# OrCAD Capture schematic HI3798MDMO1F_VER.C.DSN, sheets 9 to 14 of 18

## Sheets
9 SHEET_10: size A3
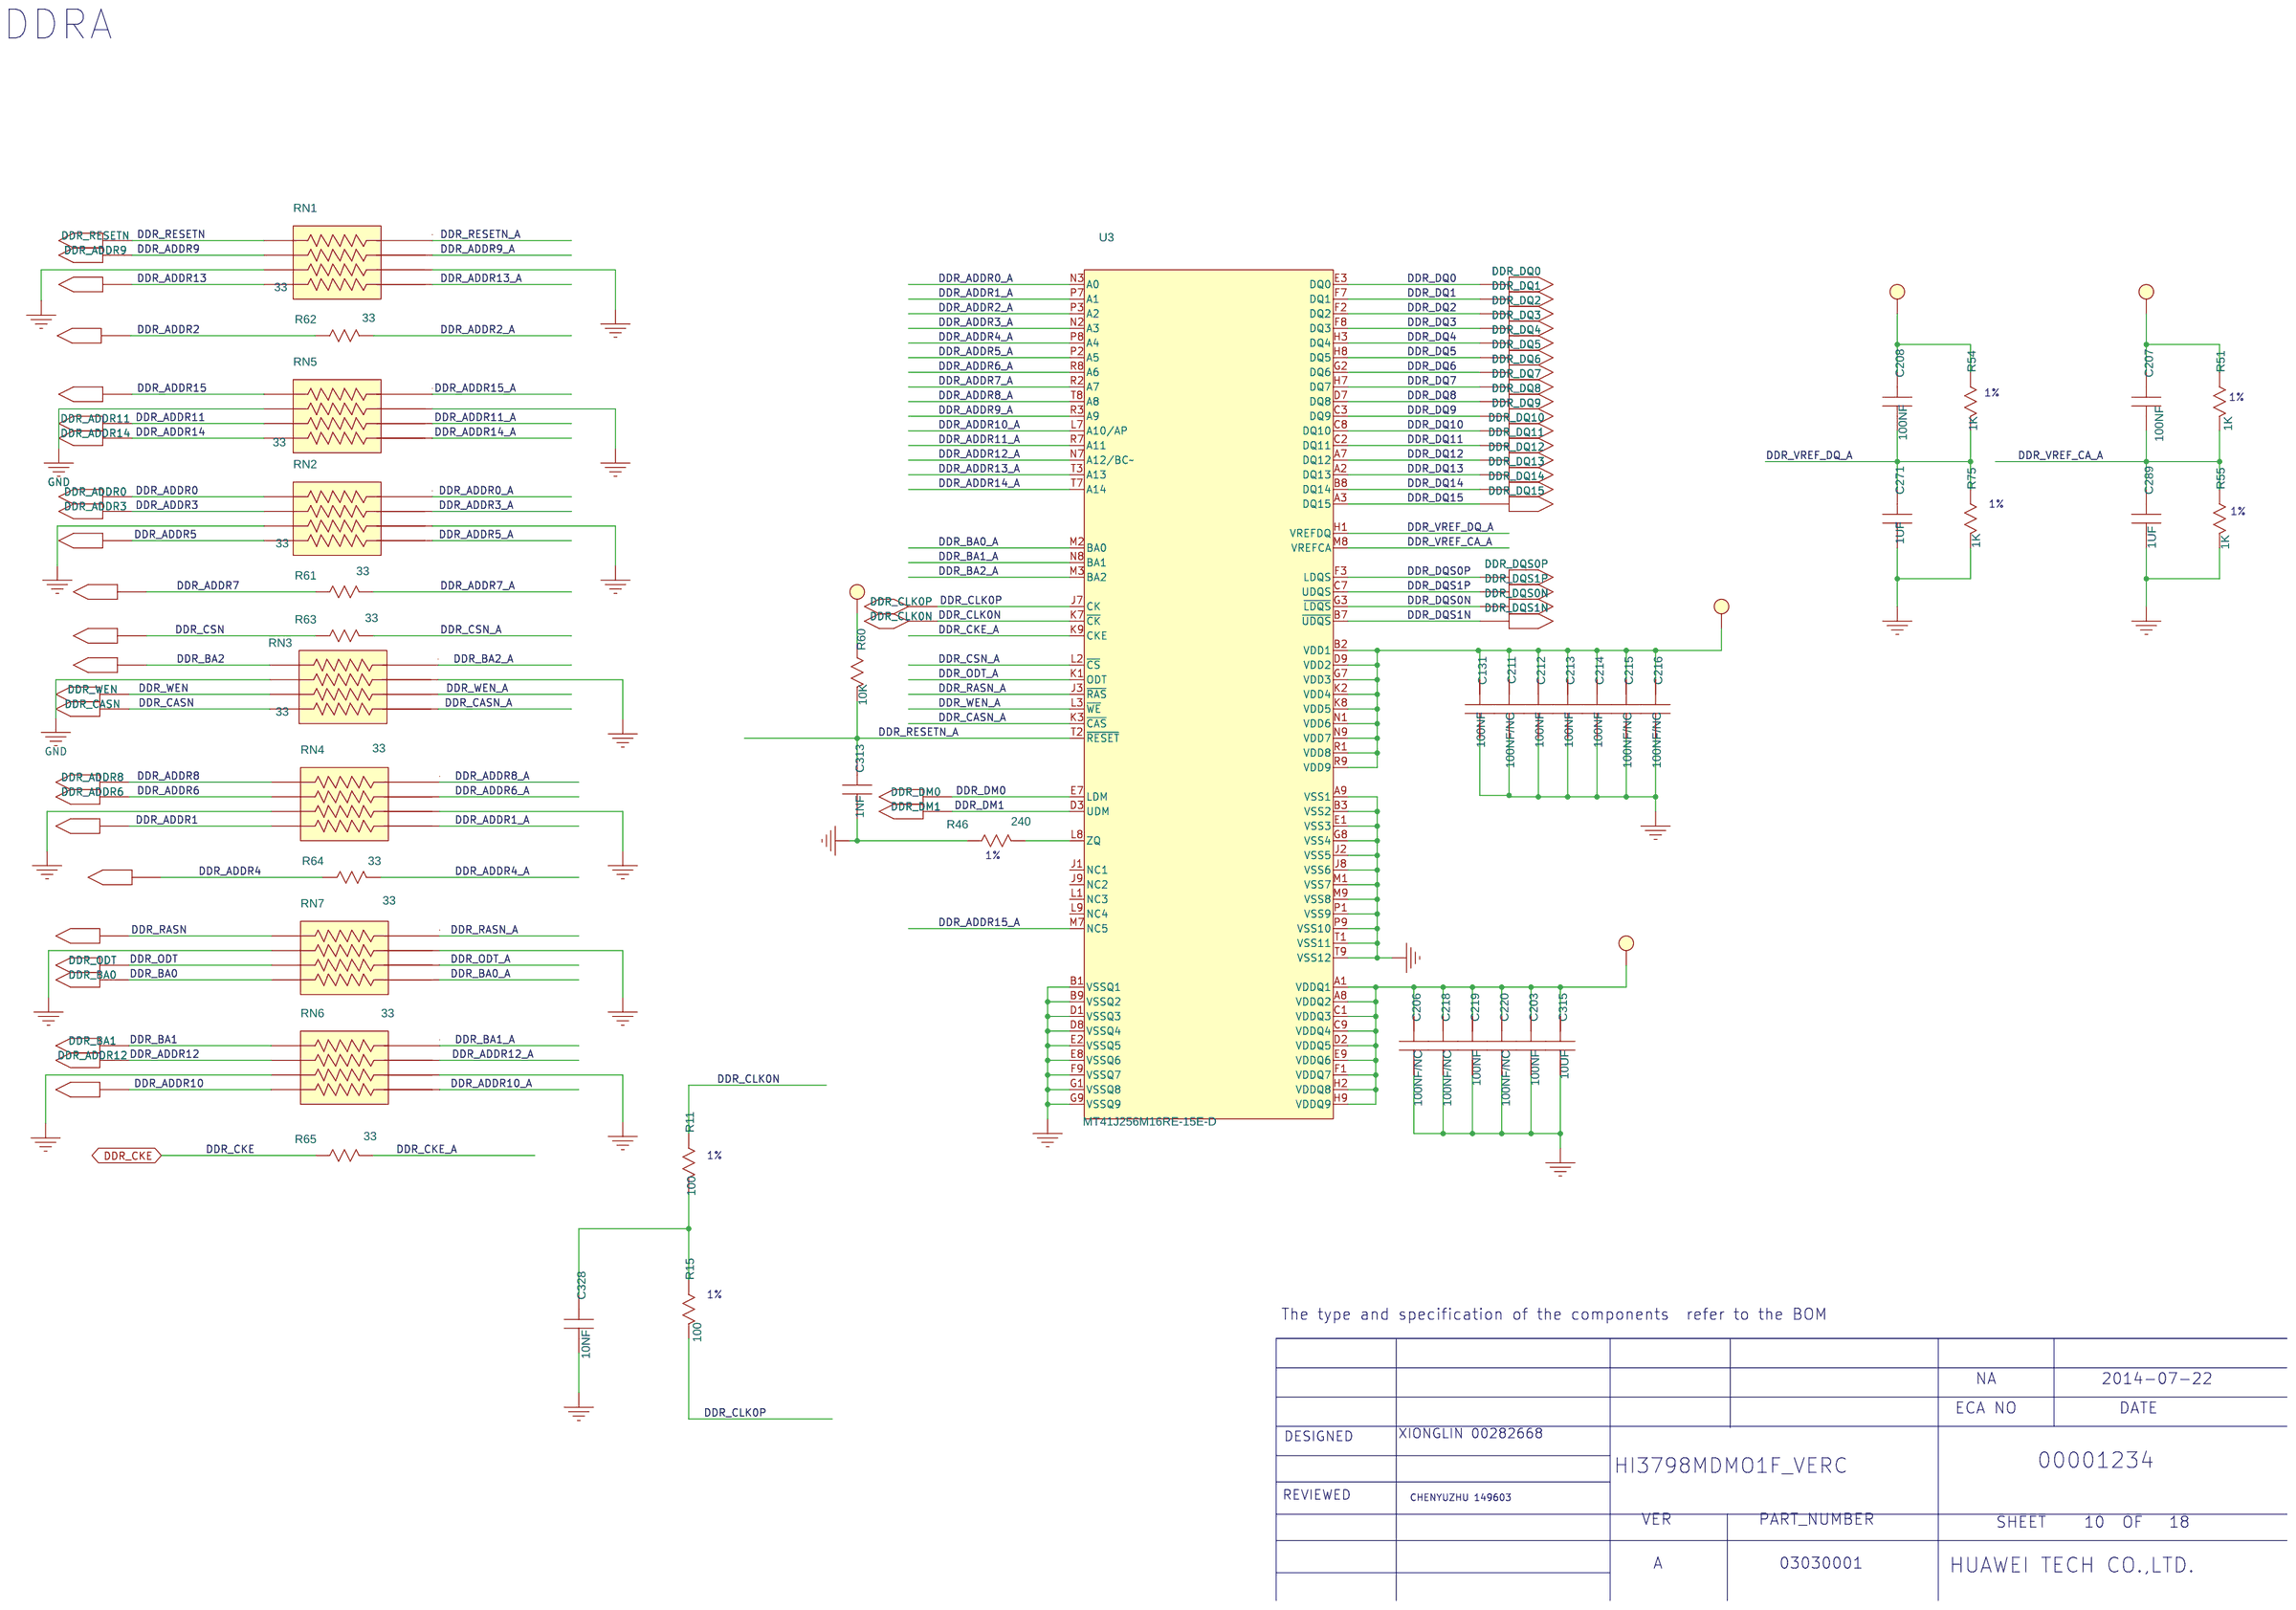
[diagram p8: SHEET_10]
10 SHEET_09: size A3
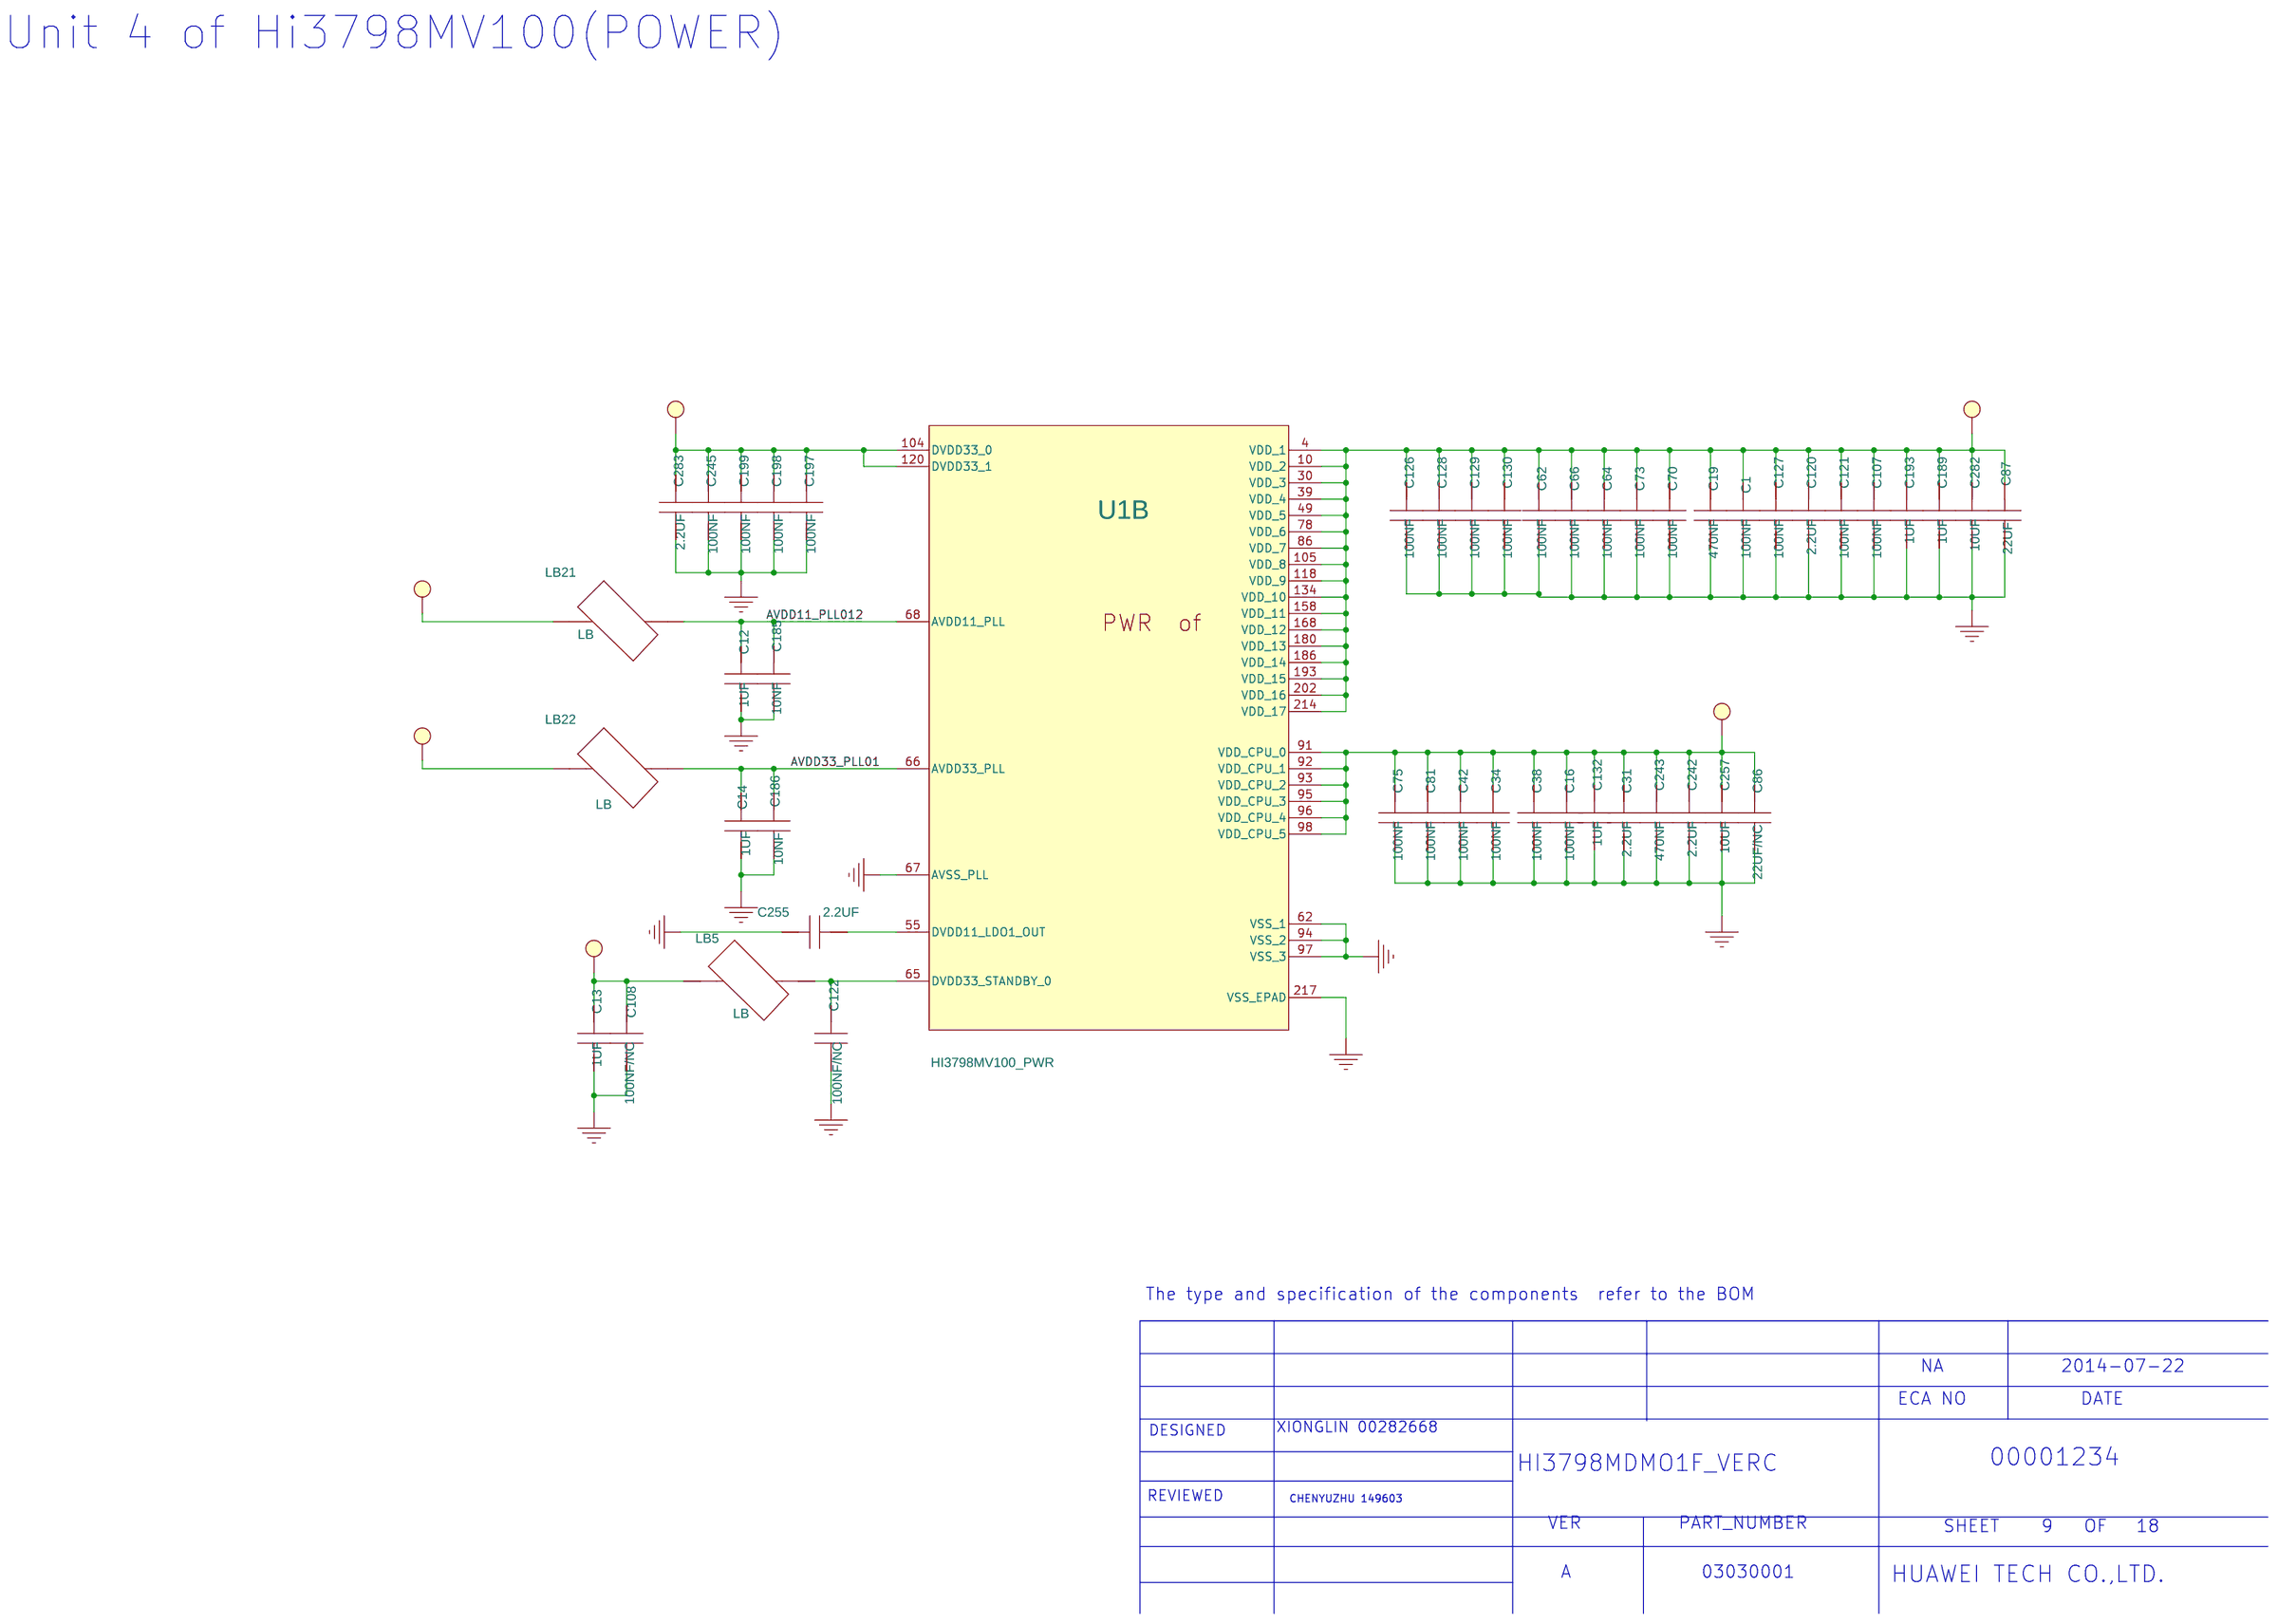
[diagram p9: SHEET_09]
11 SHEET_08: size A3
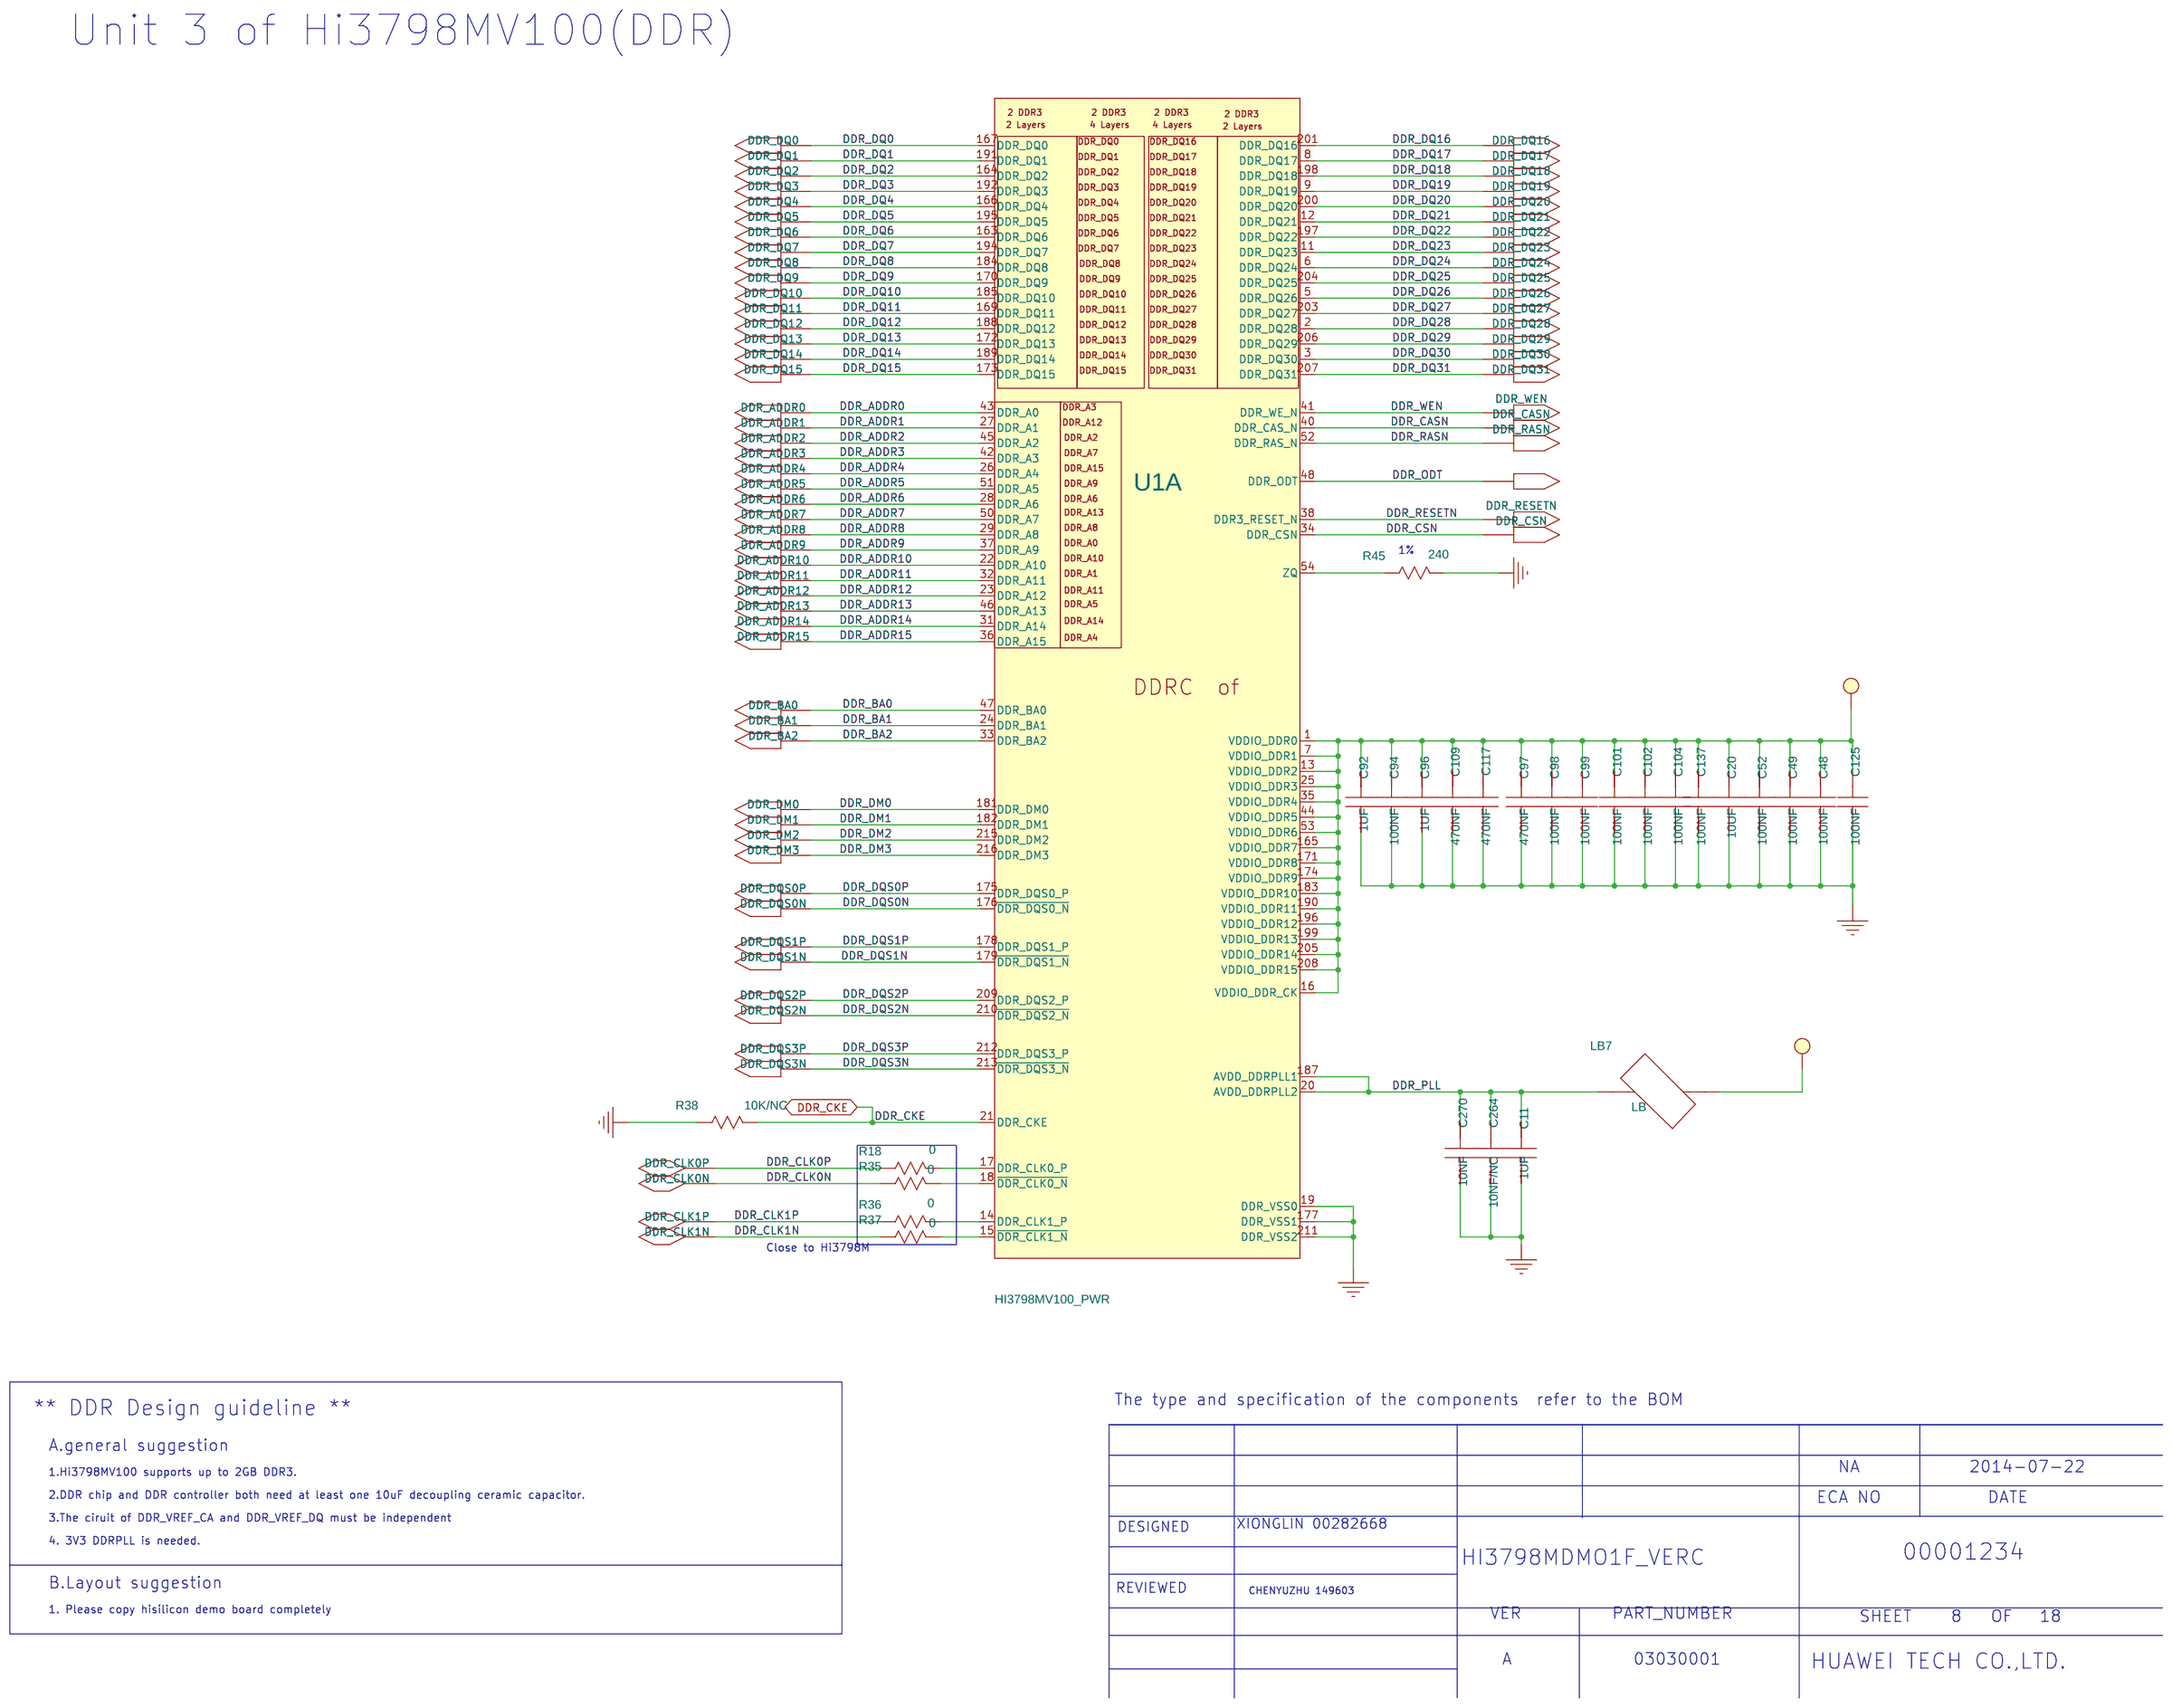
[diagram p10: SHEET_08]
12 SHEET_07: size A3
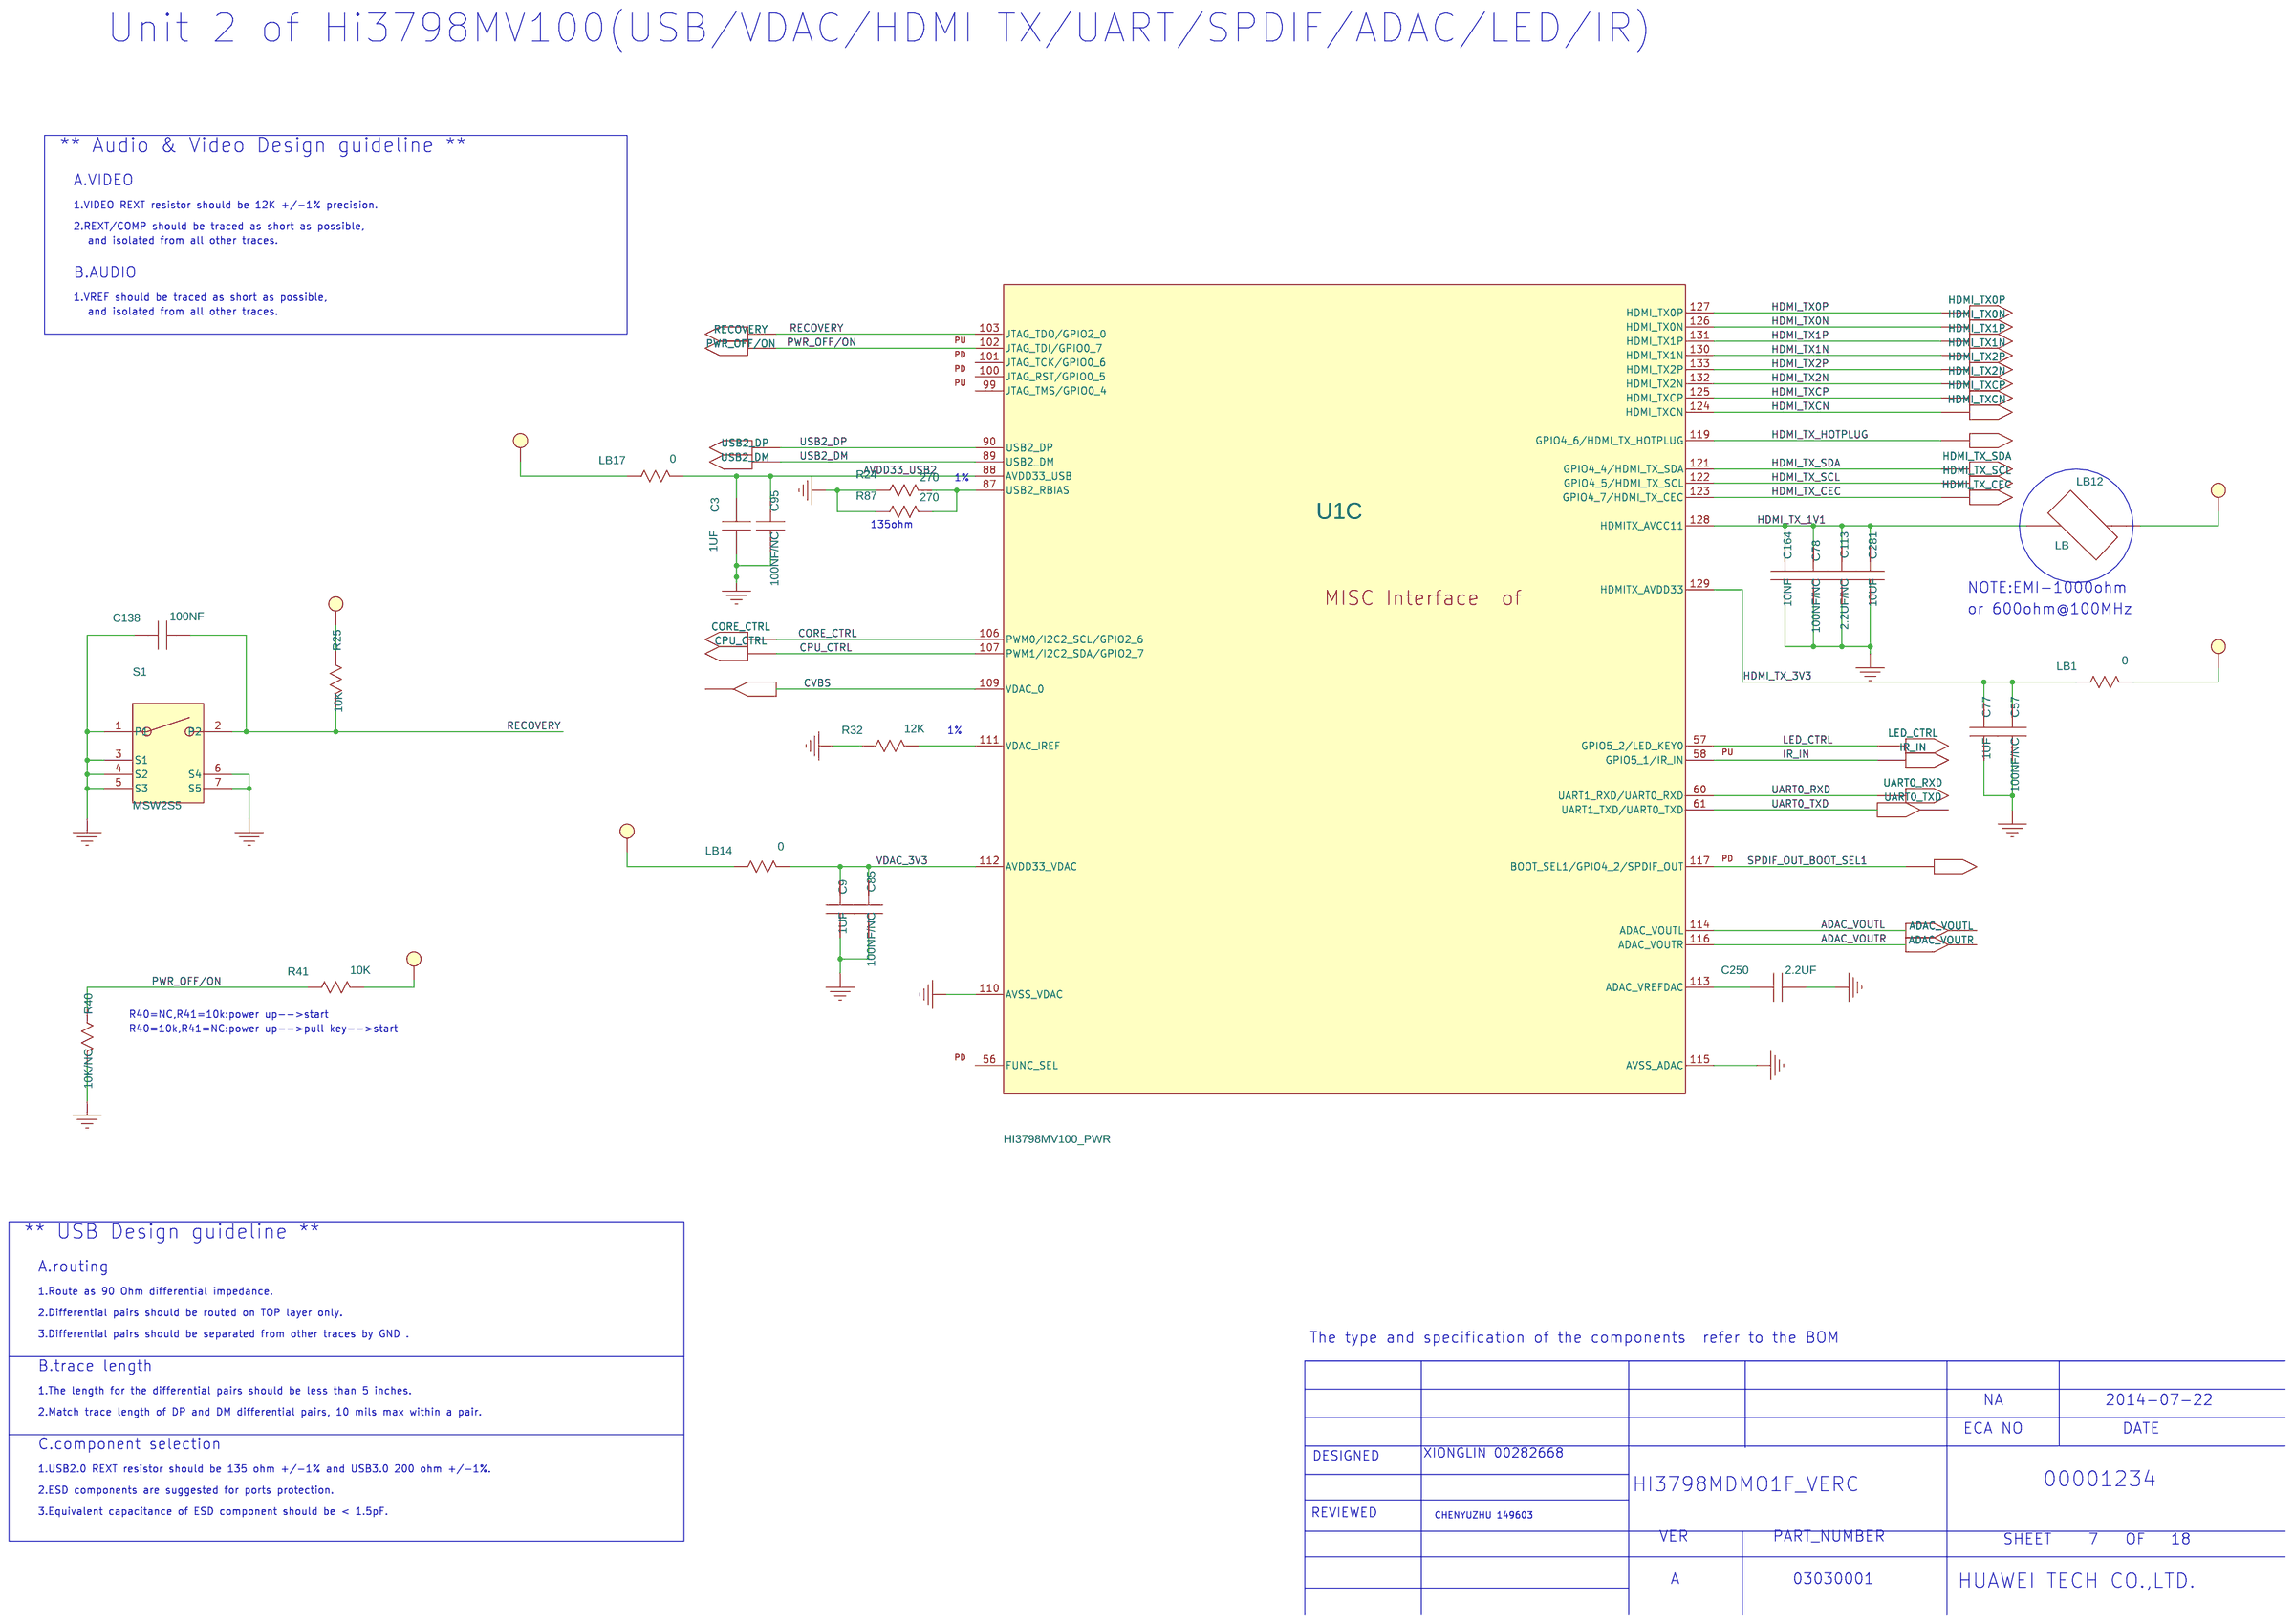
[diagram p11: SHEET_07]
13 SHEET_06: size Custom
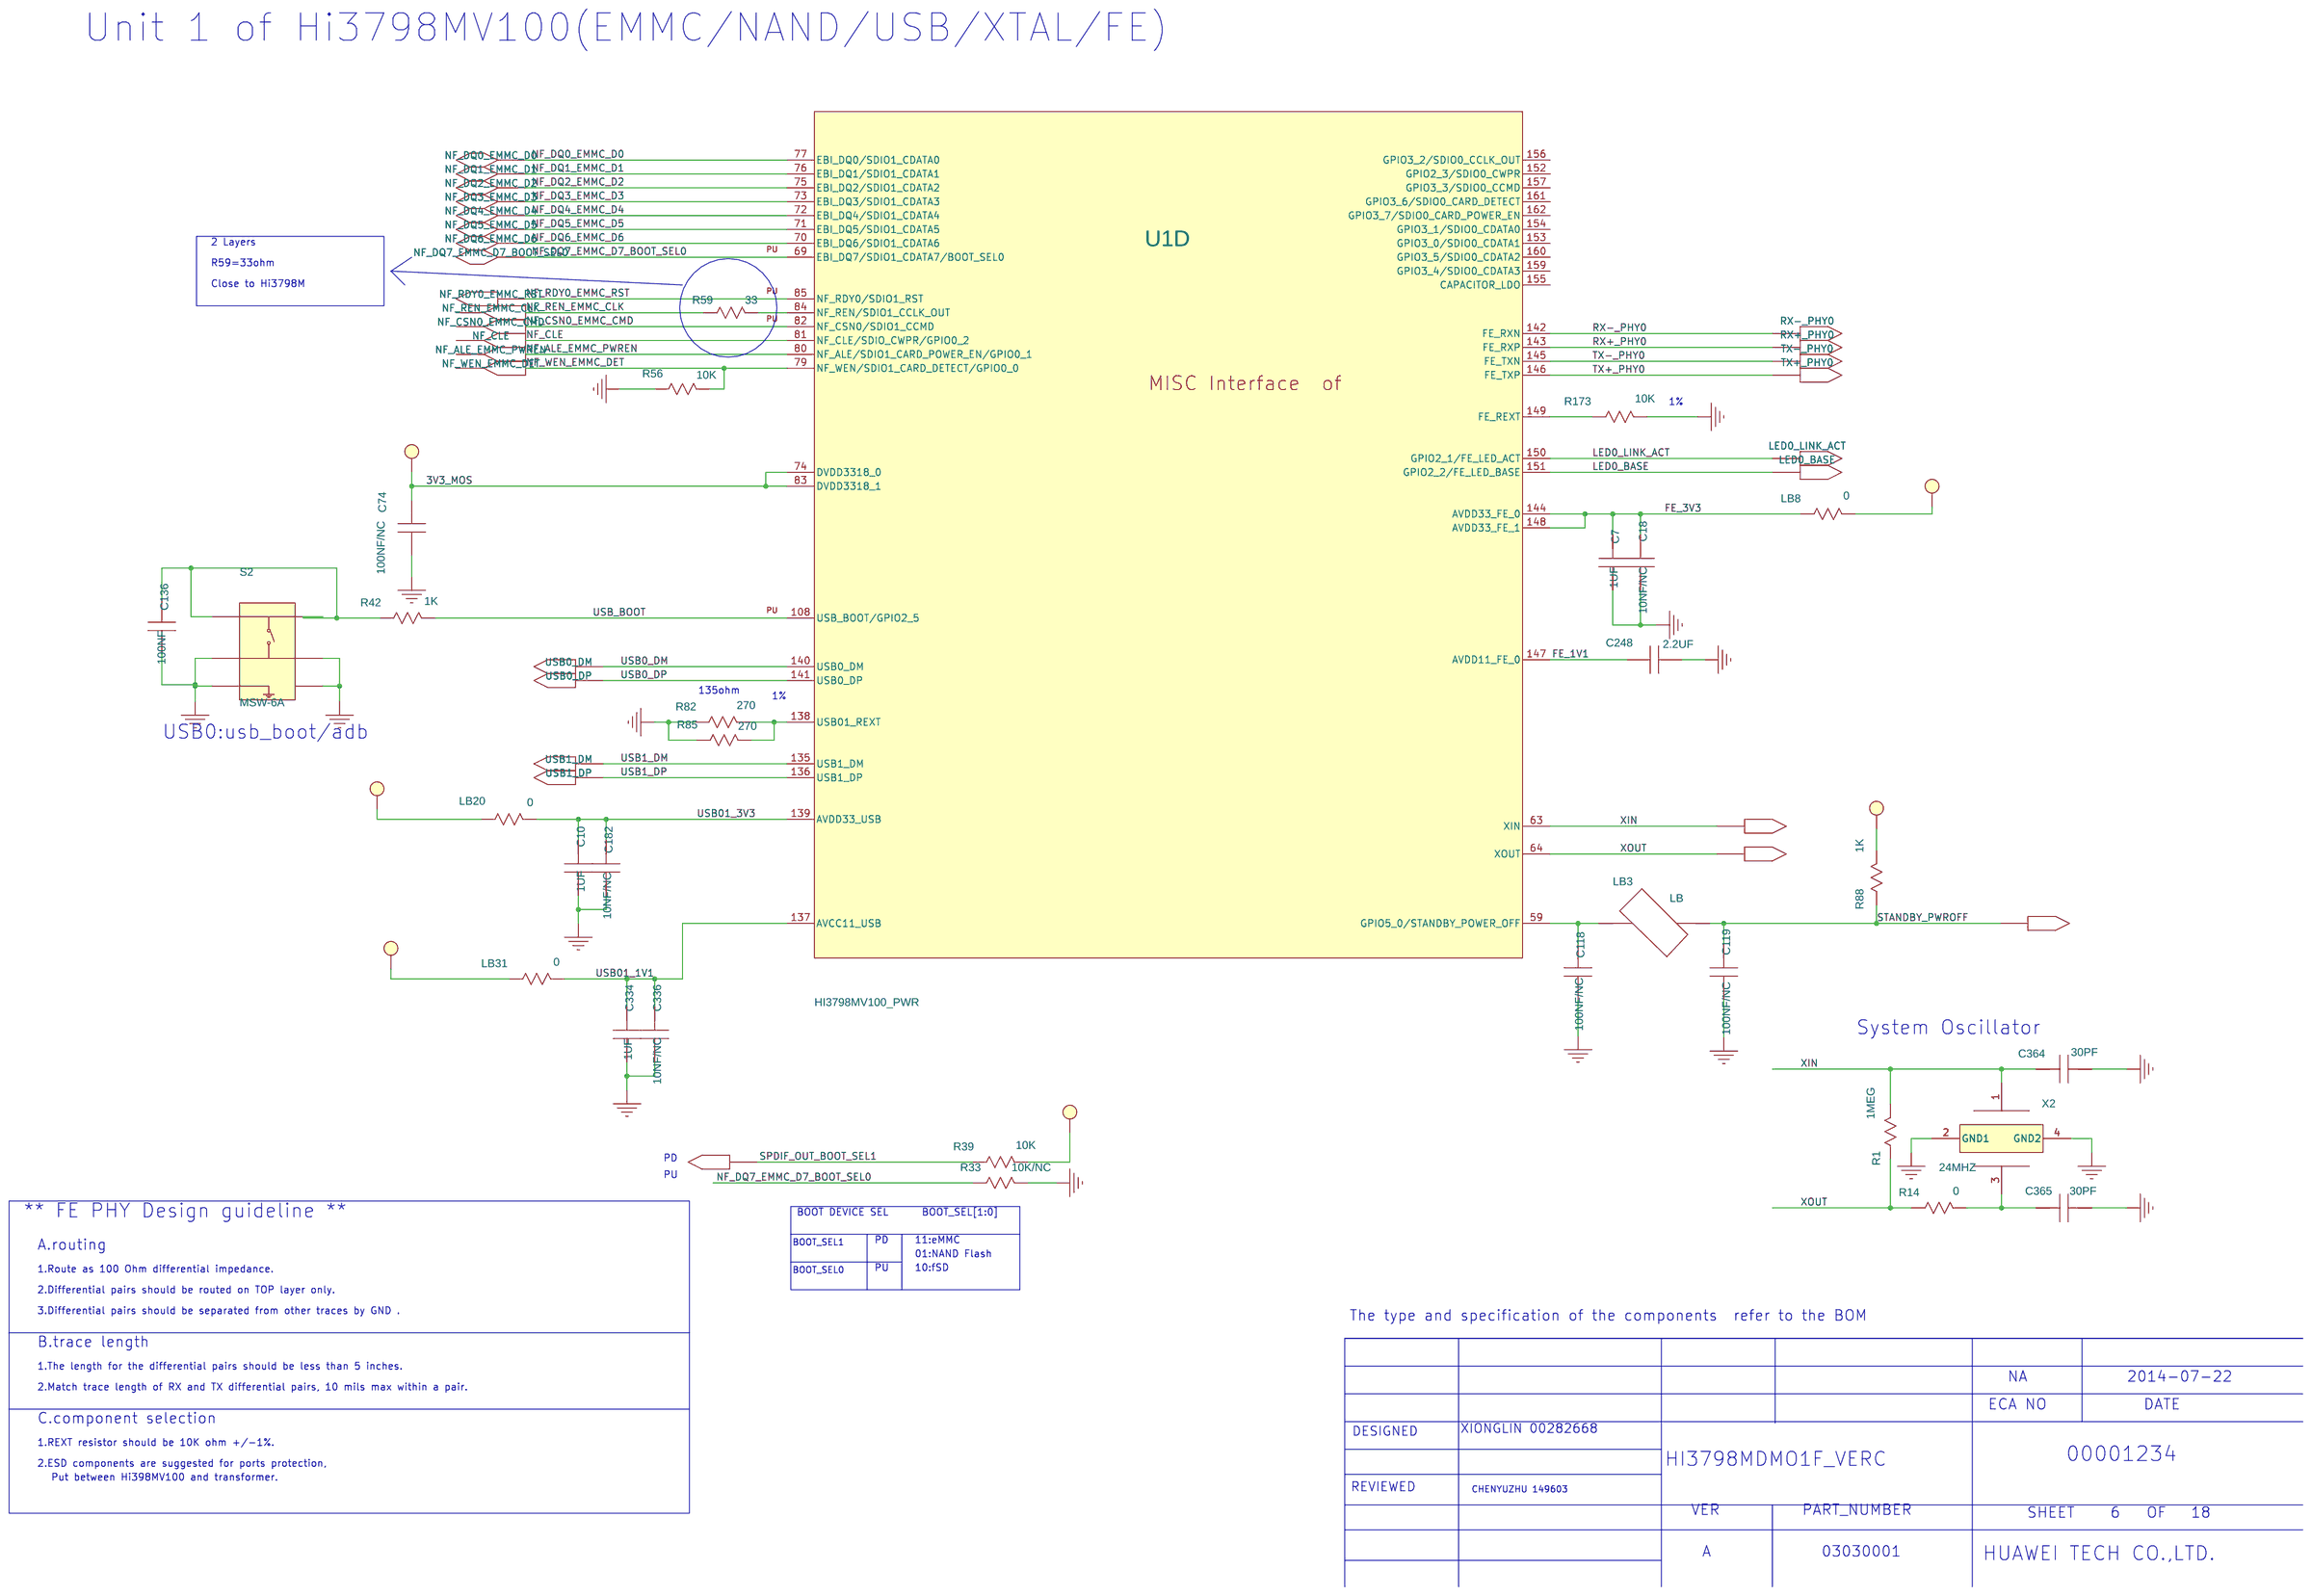
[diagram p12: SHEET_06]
14 SHEET_05: size A3
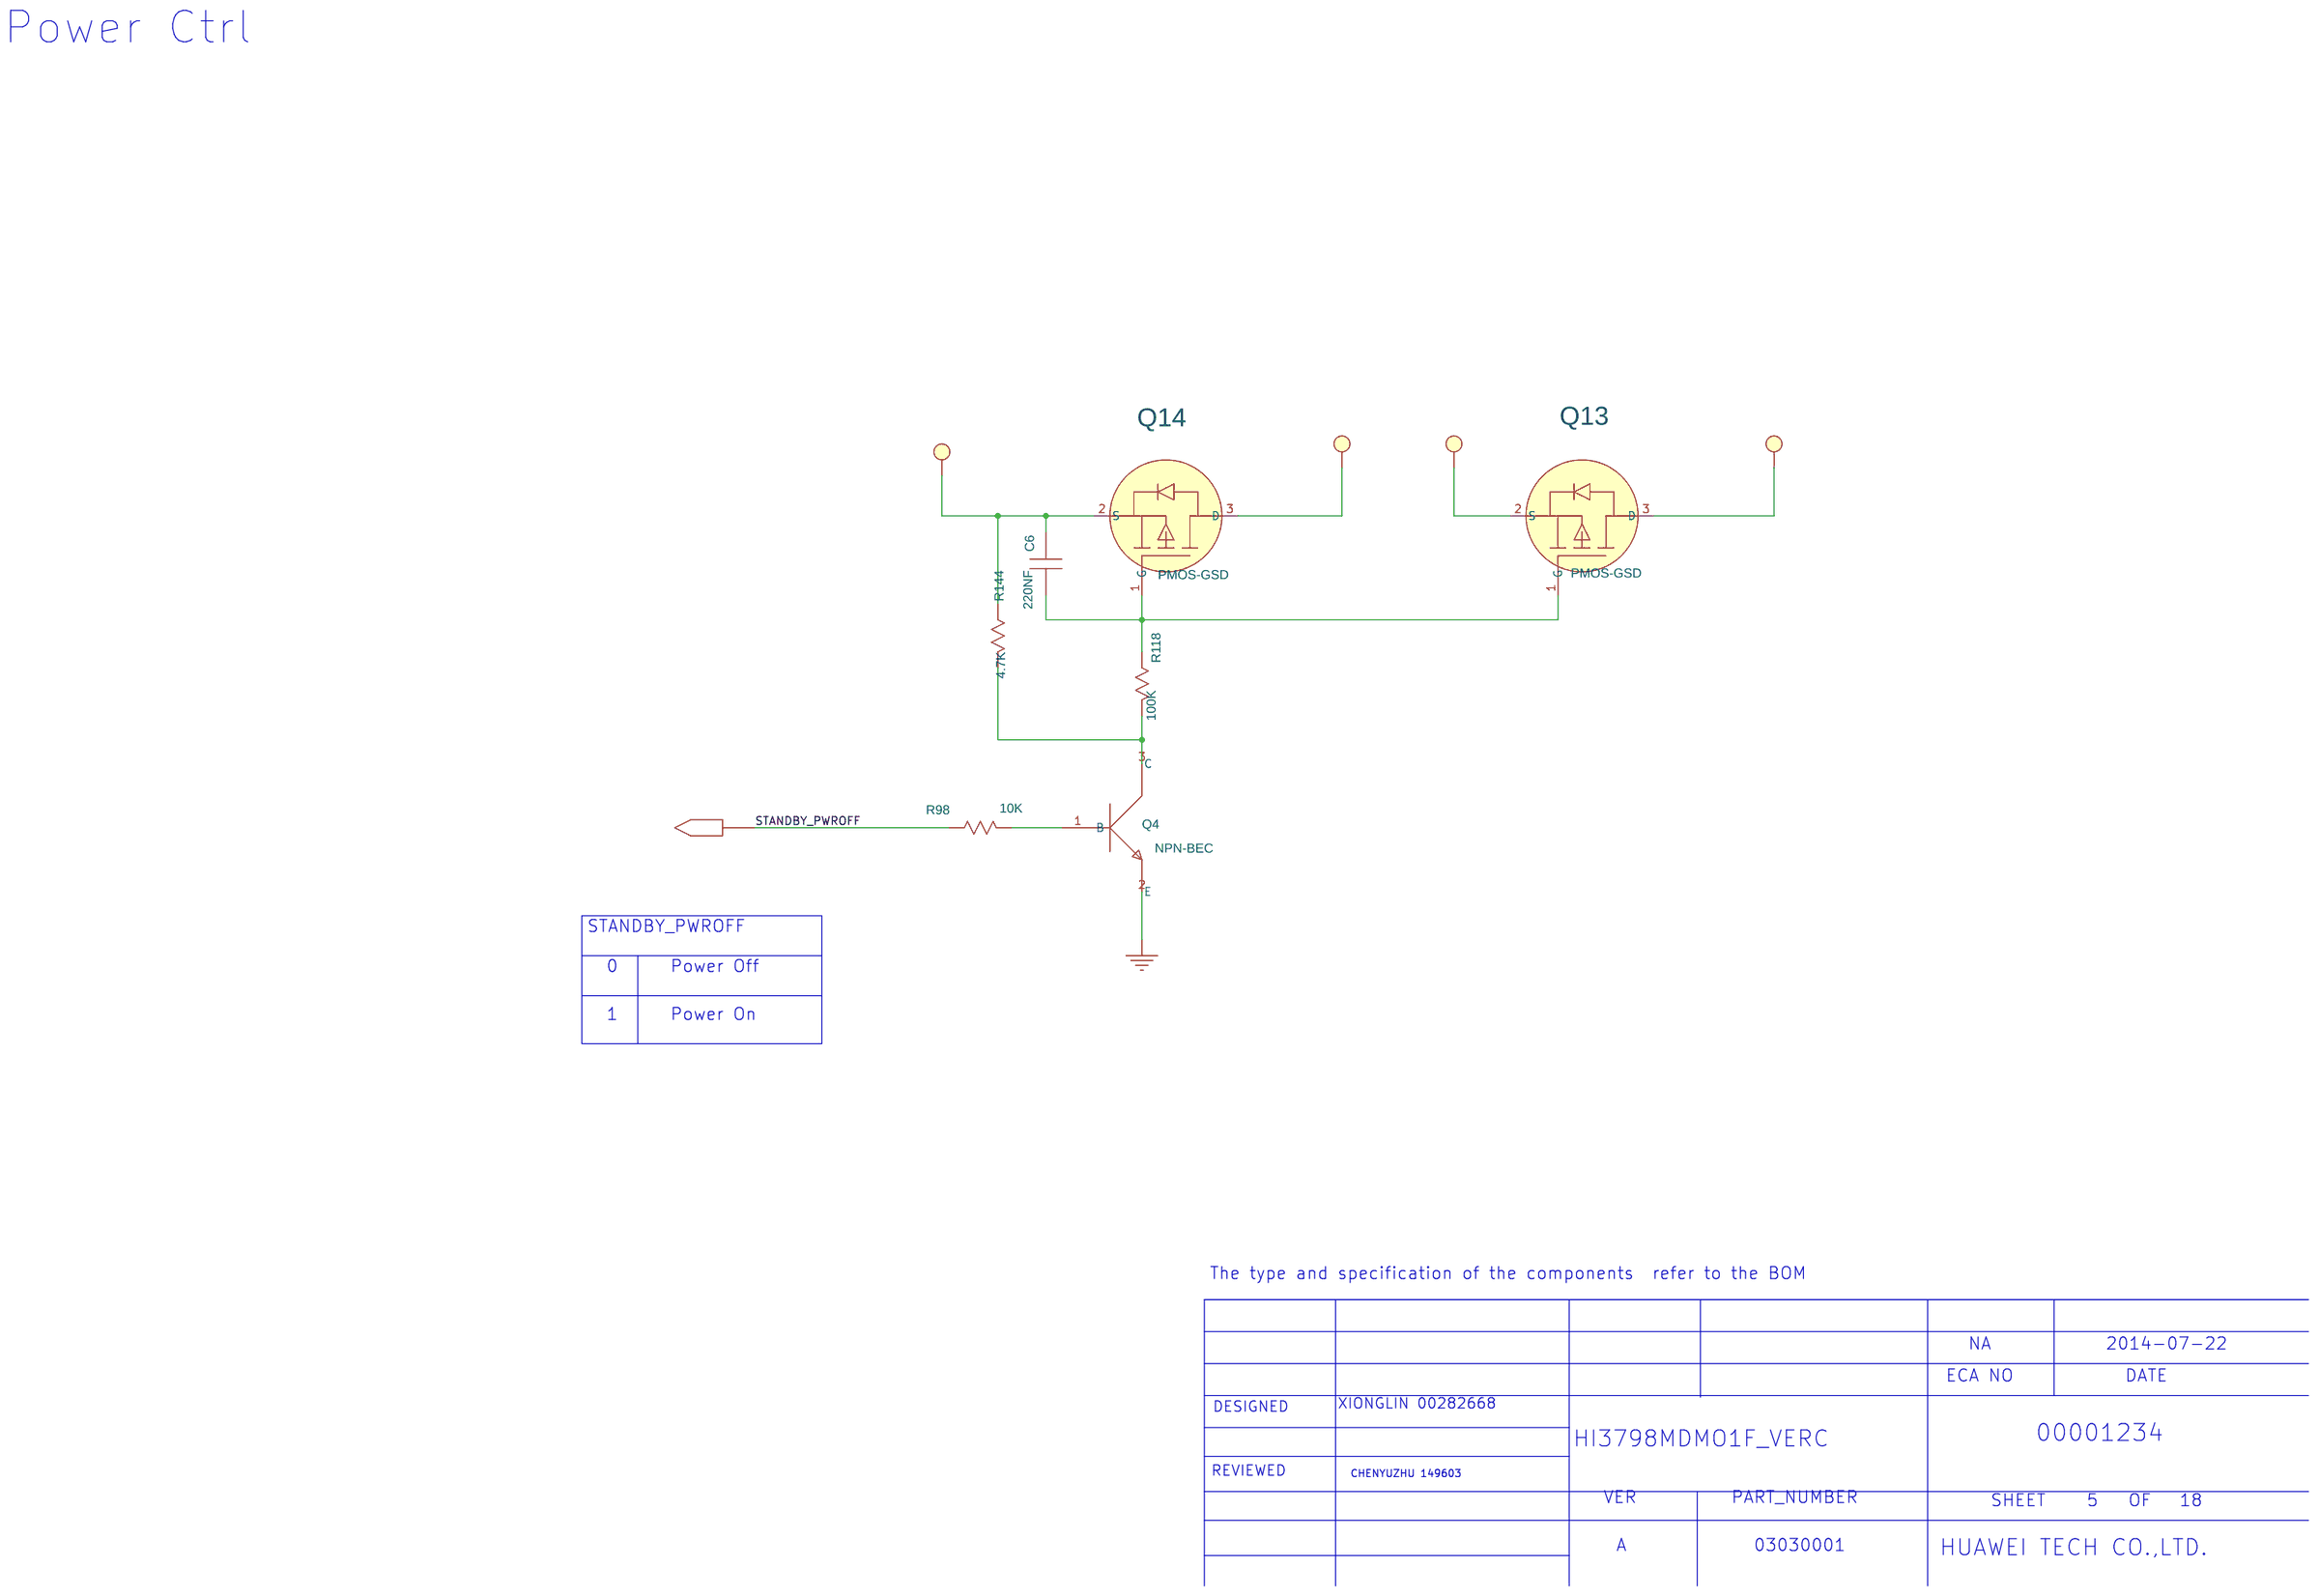
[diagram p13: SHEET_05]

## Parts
sheet SHEET_05
C6  220NF  [SC0603]
Q4  NPN-BEC  [SOT23]
Q13  PMOS-GSD  [SOT23]
Q14  PMOS-GSD  [SOT23]
R98  10K  [SR0402]
R118  100K  [SR0402]
R144  4.7K  [SR0402]
sheet SHEET_06
C7  1UF  [SC0603]
C10  1UF  [SC0603]
C18  10NF/NC  [SC0402]
C74  100NF/NC  [SC0402]
C118  100NF/NC  [SC0402]
C119  100NF/NC  [SC0402]
C136  100NF  [SC0402]
C182  10NF/NC  [SC0402]
C248  2.2UF  [HSC0402]
C334  1UF  [SC0402]
C336  10NF/NC  [SC0402]
C364  30PF  [SC0402]
C365  30PF  [SC0402]
LB3  LB  [SL0402]
LB8  0  [SL0603]
LB20  0  [SL0603]
LB31  0  [SL0402]
R1  1MEG  [SR0603]
R14  0  [SR0402]
R33  10K/NC  [SR0402]
R39  10K  [SR0402]
R42  1K  [SR0402]
R56  10K  [SR0402]
R59  33  [SR0402]
R82  270  [SR0402]
R85  270  [SR0402]
R88  1K  [SR0402]
R173  10K  [SR0402]
S2  MSW-6A  [SPSW6-T]
U1  HI3798MV100_PWR  [LQFP216-040-2424]  (sections A,B,C,D)
X2  24MHZ  [X288]
sheet SHEET_07
C3  1UF  [SC0603]
C9  1UF  [SC0603]
C57  100NF/NC  [SC0402]
C77  1UF  [SC0402]
C78  100NF/NC  [SC0402]
C85  100NF/NC  [SC0402]
C95  100NF/NC  [SC0402]
C113  2.2UF/NC  [SC0603]
C138  100NF  [SC0402]
C164  10NF  [SC0402]
C250  2.2UF  [HSC0402]
C281  10UF  [SC0603]
LB1  0  [SL0402]
LB12  LB  [SL0402]
LB14  0  [SL0603]
LB17  0  [SL0603]
R24  270  [SR0402]
R25  10K  [SR0402]
R32  12K  [SR0402]
R40  10K/NC  [SR0402]
R41  10K  [SR0402]
R87  270  [SR0402]
S1  MSW2S5  [RSTSW5-R]
sheet SHEET_08
C11  1UF  [SC0603]
C20  10UF  [SC0603]
C48  100NF  [SC0402]
C49  100NF  [SC0402]
C52  100NF  [SC0402]
C92  1UF  [SC0402]
C94  100NF  [SC0402]
C96  1UF  [SC0402]
C97  470NF  [SC0402]
C98  100NF  [SC0402]
C99  100NF  [SC0402]
C101  100NF  [SC0402]
C102  100NF  [SC0402]
C104  100NF  [SC0402]
C109  470NF  [SC0402]
C117  470NF  [SC0402]
C125  100NF  [SC0402]
C137  100NF  [SC0402]
C264  10NF/NC  [SC0402]
C270  10NF  [SC0402]
LB7  LB  [SL0603]
R18  0  [SR0402]
R35  0  [SR0402]
R36  0  [SR0402]
R37  0  [SR0402]
R38  10K/NC  [SR0402]
R45  240  [SR0402]
sheet SHEET_09
C1  100NF  [SC0402]
C12  1UF  [SC0402]
C13  1UF  [SC0603]
C14  1UF  [SC0402]
C16  100NF  [SC0402]
C19  470NF  [SC0402]
C31  2.2UF  [HSC0402]
C34  100NF  [SC0402]
C38  100NF  [SC0402]
C42  100NF  [SC0402]
C62  100NF  [SC0402]
C64  100NF  [SC0402]
C66  100NF  [SC0402]
C70  100NF  [SC0402]
C73  100NF  [SC0402]
C75  100NF  [SC0402]
C81  100NF  [SC0402]
C86  22UF/NC  [SC1206]
C87  22UF  [SC1206]
C107  100NF  [SC0402]
C108  100NF/NC  [SC0402]
C120  2.2UF  [HSC0402]
C121  100NF  [SC0402]
C122  100NF/NC  [SC0402]
C126  100NF  [SC0402]
C127  100NF  [SC0402]
C128  100NF  [SC0402]
C129  100NF  [SC0402]
C130  100NF  [SC0402]
C132  1UF  [SC0402]
C185  10NF  [SC0402]
C186  10NF  [SC0402]
C189  1UF  [SC0402]
C193  1UF  [SC0402]
C197  100NF  [SC0402]
C198  100NF  [SC0402]
C199  100NF  [SC0402]
C242  2.2UF  [HSC0402]
C243  470NF  [SC0402]
C245  100NF  [SC0402]
C255  2.2UF  [HSC0402]
C257  10UF  [SC0603]
C282  10UF  [SC0603]
C283  2.2UF  [SC0603]
LB5  LB  [SL0402]
LB21  LB  [SL0603]
LB22  LB  [SL0603]
sheet SHEET_10
C131  100NF  [SC0402]
C203  100NF  [SC0402]
C206  100NF/NC  [SC0402]
C207  100NF  [SC0402]
C208  100NF  [SC0402]
C211  100NF/NC  [SC0402]
C212  100NF  [SC0402]
C213  100NF  [SC0402]
C214  100NF  [SC0402]
C215  100NF/NC  [SC0402]
C216  100NF/NC  [SC0402]
C218  100NF/NC  [SC0402]
C219  100NF  [SC0402]
C220  100NF/NC  [SC0402]
C271  1UF  [SC0402]
C289  1UF  [SC0402]
C313  1NF  [SC0402]
C315  10UF  [SC0603]
C328  10NF  [SC0402]
R11  100  [SR0402]
R15  100  [SR0402]
R46  240  [SR0402]
R51  1K  [SR0402]
R54  1K  [SR0402]
R55  1K  [SR0402]
R60  10K  [SR0402]
R61  33  [SR0402]
R62  33  [SR0402]
R63  33  [SR0402]
R64  33  [SR0402]
R65  33  [SR0402]
R75  1K  [SR0402]
RN1  33  [SRN8-0804]
RN2  33  [SRN8-0804]
RN3  33  [SRN8-0804]
RN4  33  [SRN8-0804]
RN5  33  [SRN8-0804]
RN6  33  [SRN8-0804]
RN7  33  [SRN8-0804]
U3  MT41J256M16RE-15E-D  [BGA96-32-1609I]

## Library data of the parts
C6 = C: %182%%238%%182%%168%%185%%164%%215%%247%%181%%231%%209%%185%(V): 10; %195%%232%%202%%246%: SMD陶瓷电容-10V-220NF-+/-10%-X7R-0603-供电专用-供电专用; %208%%161%%192%%224%%195%%251%%179%%198%: SMD陶瓷电容; CODE: 8070856; COMPONENT_HIGH_MAX: 0.9MM; DEVICE: C0603C224K8RAC7867
Q4 = NPN-BEC: %195%%232%%202%%246%: 三极管-NPN-45V-100MA-225MW-200MV@100MA-SOT-23-180@2MA; %208%%161%%192%%224%%195%%251%%179%%198%: 三极管; CODE: 15050206; COMPONENT_HIGH_MAX: 1.26MM; DEVICE: BC847AE6327
Q13 Q14 = FETP-GSD: %195%%232%%202%%246%: MOSFET-P沟道--8V--3A-50MOHM--8V-SOT23; %208%%161%%192%%224%%195%%251%%179%%198%: MOSFET; CODE: 15060134; COMPONENT_HIGH_MAX: 1.11MM; DEVICE: IRLML6401TR
R98 = R: %182%%238%%182%%168%%185%%166%%194%%202%(W): 0.06; %195%%232%%202%%246%: 片式厚膜电阻器-0.0625W-10000OHM-±5%-0402; %208%%161%%192%%224%%195%%251%%179%%198%: 片式厚膜电阻器; %215%%232%%214%%181%%212%%202%%208%%237%%198%%171%%178%%238%: ±5%; CODE: 7090815; COMPONENT_HIGH_MAX: 0.4MM; DEVICE: RC_02W103JT
R118 = R: %182%%238%%182%%168%%185%%166%%194%%202%(W): 0.06; %195%%232%%202%%246%: 片式厚膜电阻器-0.0625W-100000OHM-+/-5%-0402-BT; %208%%161%%192%%224%%195%%251%%179%%198%: 片式厚膜电阻器; %215%%232%%214%%181%%212%%202%%208%%237%%198%%171%%178%%238%: +/-5%; CODE: 7090831; COMPONENT_HIGH_MAX: 0.4MM; DEVICE: RK73B1ELTP104J
R144 = R: %182%%238%%182%%168%%185%%166%%194%%202%(W): 0.06; %195%%232%%202%%246%: 片式厚膜电阻器-0.0625W-4700OHM-+/-5%-0402-BT; %208%%161%%192%%224%%195%%251%%179%%198%: 片式厚膜电阻器; %215%%232%%214%%181%%212%%202%%208%%237%%198%%171%%178%%238%: +/-5%; CODE: 7090793; COMPONENT_HIGH_MAX: 0.4MM; DEVICE: RK73B1ELTP472J
C3 C7 C9-C11 C13 = C: %182%%238%%182%%168%%185%%164%%215%%247%%181%%231%%209%%185%(V): 25; %195%%232%%202%%246%: SMD陶瓷电容-25V-1000NF-+/-10%-X7R-0603; %208%%161%%192%%224%%195%%251%%179%%198%: SMD陶瓷电容; CODE: 8070962; COMPONENT_HIGH_MAX: 0.9MM; DEVICE: CETMK107B7105KA_T
C1 C16 C18 C34 C38 C42 C48 C49 C52 C57 C62 C64 C66 C70 C73-C75 C78 C81 C85 C95 C98 C99 C101 C102 C104 C107 C108 C118 C119 C121 C122 C125-C131 C136-C138 C197-C199 C203 C206-C208 C211-C216 C218-C220 C245 = C: %182%%238%%182%%168%%185%%164%%215%%247%%181%%231%%209%%185%(V): 10; %195%%232%%202%%246%: SMD陶瓷电容-10V-100NF-+/-10%-X5R-0402; %208%%161%%192%%224%%195%%251%%179%%198%: SMD陶瓷电容; CODE: 8070561; COMPONENT_HIGH_MAX: 0.55MM; DEVICE: C0402C104K8PAC_7867
C164 C182 C185 C186 C264 C270 C336 = C: %182%%238%%182%%168%%185%%164%%215%%247%%181%%231%%209%%185%(V): 16; %195%%232%%202%%246%: SMD陶瓷电容-16V-10NF-+/-10%-X7R-0402-BT,TS16949; %208%%161%%192%%224%%195%%251%%179%%198%: SMD陶瓷电容; CODE: 8070449; COMPONENT_HIGH_MAX: 0.55MM; DEVICE: GRM155R71C103KA01D
C31 C120 C242 C248 C250 C255 = C: %182%%238%%182%%168%%185%%164%%215%%247%%181%%231%%209%%185%(V): 6.3; %195%%232%%202%%246%: SMD陶瓷电容-6.3V-2200NF-+/-20%-X5R-0402-TS16949; %208%%161%%192%%224%%195%%251%%179%%198%: SMD陶瓷电容; CODE: 8070667; COMPONENT_HIGH_MAX: 0.6MM; DEVICE: GRM155R60J225ME15D
C12 C14 C77 C92 C94 C96 C132 C189 C193 C271 C289 C334 = C: %182%%238%%182%%168%%185%%164%%215%%247%%181%%231%%209%%185%(V): 10; %195%%232%%202%%246%: SMD陶瓷电容-10V-1000NF-+/-10%-X5R-0402-BT,TS16949; %208%%161%%192%%224%%195%%251%%179%%198%: SMD陶瓷电容; CODE: 8070612; COMPONENT_HIGH_MAX: 0.55MM; DEVICE: CV05X5R105K10AH
C364 C365 = C: %182%%238%%182%%168%%185%%164%%215%%247%%181%%231%%209%%185%(V): 50; %195%%232%%202%%246%: SMD陶瓷电容-50V-0.03NF-+/-5%-NPO-0402; %208%%161%%192%%224%%195%%251%%179%%198%: SMD陶瓷电容; CODE: 8070604; COMPONENT_HIGH_MAX: 0.55MM; DEVICE: GRM1555C1H300J
LB3 LB5 = LB: %195%%232%%202%%246%: EMI磁珠-+/-25%-600OHM-0.65OHM-0.2A-402; %208%%161%%192%%224%%195%%251%%179%%198%: EMI磁珠; CODE: 10070013; COMPONENT_HIGH_MAX: 0.55MM; DEVICE: BLM15BD601SN1D
LB8 LB14 LB17 LB20 = R: %182%%238%%182%%168%%185%%166%%194%%202%(W): 0.1; %195%%232%%202%%246%: 片式厚膜电阻器-0.1W-0OHM-<50MOHM-0603-1A-BT,TS16949; %208%%161%%192%%224%%195%%251%%179%%198%: 片式厚膜电阻器; %215%%232%%214%%181%%212%%202%%208%%237%%198%%171%%178%%238%: <50MOHM; CODE: 7090522; COMPONENT_HIGH_MAX: 0.6MM; DEVICE: RC0603JR_070RL
LB1 LB31 R18 R35-R37 = R: %182%%238%%182%%168%%185%%166%%194%%202%(W): 0.06; %195%%232%%202%%246%: 片式厚膜电阻器-0.0625W-0OHM-< 50MOHM-0402-1A-BT; %208%%161%%192%%224%%195%%251%%179%%198%: 片式厚膜电阻器; %215%%232%%214%%181%%212%%202%%208%%237%%198%%171%%178%%238%: < 50MOHM; CODE: 7090800; COMPONENT_HIGH_MAX: 0.4MM; DEVICE: RC0402JR_070R
R1 = R: %182%%238%%182%%168%%185%%166%%194%%202%(W): 0.1; %195%%232%%202%%246%: 片式厚膜电阻器-0.1W-1000000OHM-±5%-0603; %208%%161%%192%%224%%195%%251%%179%%198%: 片式厚膜电阻器; %215%%232%%214%%181%%212%%202%%208%%237%%198%%171%%178%%238%: ±5%; CODE: 7090263; DEVICE: RC0603JR_071M
R14 = R: %182%%238%%182%%168%%185%%166%%194%%202%(W): 0.06; %195%%232%%202%%246%: 片式厚膜电阻器-0.0625W-0OHM-< 50MOHM-0402-1A-BT; %208%%161%%192%%224%%195%%251%%179%%198%: 片式厚膜电阻器; %215%%232%%214%%181%%212%%202%%208%%237%%198%%171%%178%%238%: < 50MOHM; CODE: 7090800; DEVICE: RC0402JR_070R
R25 R33 R38-R41 = R: %182%%238%%182%%168%%185%%166%%194%%202%(W): 0.06; %195%%232%%202%%246%: 片式厚膜电阻器-0.0625W-10000OHM-+/-5%-0402-BT; %208%%161%%192%%224%%195%%251%%179%%198%: 片式厚膜电阻器; %215%%232%%214%%181%%212%%202%%208%%237%%198%%171%%178%%238%: +/-5%; CODE: 7090815; COMPONENT_HIGH_MAX: 0.4MM; DEVICE: RC_02W103JT
R42 R88 = R: %182%%238%%182%%168%%185%%166%%194%%202%(W): 0.06; %195%%232%%202%%246%: 片式厚膜电阻器-0.0625W-1000OHM-+/-5%-0402-BT; %208%%161%%192%%224%%195%%251%%179%%198%: 片式厚膜电阻器; %215%%232%%214%%181%%212%%202%%208%%237%%198%%171%%178%%238%: +/-5%; CODE: 7090809; COMPONENT_HIGH_MAX: 0.4MM; DEVICE: RC0402JR_071KL
R56 R60 = R: %182%%238%%182%%168%%185%%166%%194%%202%(W): 0.06; %195%%232%%202%%246%: 片式厚膜电阻器-0.0625W-10000OHM-+/-5%-0402-BT; %208%%161%%192%%224%%195%%251%%179%%198%: 片式厚膜电阻器; %215%%232%%214%%181%%212%%202%%208%%237%%198%%171%%178%%238%: +/-5%; CODE: 7090815; DEVICE: RC_02W103JT
R59 R61-R65 = R: %182%%238%%182%%168%%185%%166%%194%%202%(W): 0.06; %195%%232%%202%%246%: 片式厚膜电阻器-0.0625W-33OHM-+/-1%-0402; %208%%161%%192%%224%%195%%251%%179%%198%: 片式厚膜电阻器; %215%%232%%214%%181%%212%%202%%208%%237%%198%%171%%178%%238%: +/-1%; CODE: 7090836; COMPONENT_HIGH_MAX: 0.4MM; DEVICE: RC0402FR_0733RL
R24 R82 R85 R87 = R: %182%%238%%182%%168%%185%%166%%194%%202%(W): 0.06; %195%%232%%202%%246%: 片式厚膜电阻器-0.0625W-270OHM-+/-5%-0402; %208%%161%%192%%224%%195%%251%%179%%198%: 片式厚膜电阻器; %215%%232%%214%%181%%212%%202%%208%%237%%198%%171%%178%%238%: +/-5%; CODE: 7090609; COMPONENT_HIGH_MAX: 0.4MM; DEVICE: RC0402JR_07270R
R173 = R: %182%%238%%182%%168%%185%%166%%194%%202%(W): 0.06; %195%%232%%202%%246%: 片式厚膜电阻器-0.0625W-10000OHM-+/-1%-0402-BT; %208%%161%%192%%224%%195%%251%%179%%198%: 片式厚膜电阻器; %215%%232%%214%%181%%212%%202%%208%%237%%198%%171%%178%%238%: +/-1%; CODE: 7090867; COMPONENT_HIGH_MAX: 0.4MM; DEVICE: RK73H1ETTP1002F
S2 = MSW-6A: %195%%232%%202%%246%: 微动开关-SPST-12VDC-0.05A-贴片-0.5MM-5.2*5.2*1.5MM-1,000,000; %208%%161%%192%%224%%195%%251%%179%%198%: 微动开关; COMPONENT_HIGH_MAX: 1.71MM; DEVICE: TMG_533_T_R
U1 = HI3798MV100_PWR_8: CaptureCellPackProp: HI3798MV100_PWRA
X2 = X_B: %195%%232%%202%%246%: 晶体谐振器-24MHZ; %208%%161%%192%%224%%195%%251%%179%%198%: 晶体谐振器; CODE: 12020151; COMPONENT_HIGH_MAX: 1MM; DEVICE: E5SB400000F15D11
C113 C283 = C: %182%%238%%182%%168%%185%%164%%215%%247%%181%%231%%209%%185%(V): 10; %195%%232%%202%%246%: SMD陶瓷电容-10V-2200NF-+/-10%-X5R-0603; %208%%161%%192%%224%%195%%251%%179%%198%: SMD陶瓷电容; CODE: 8070573; COMPONENT_HIGH_MAX: 0.9MM; DEVICE: GRM188R61A225KE34D
C20 C257 C281 C282 C315 = C: %182%%238%%182%%168%%185%%164%%215%%247%%181%%231%%209%%185%(V): 6.3; %195%%232%%202%%246%: SMD陶瓷电容-6.3V-10000NF-+/-20%-X5R-0603-BT,TS16949; %208%%161%%192%%224%%195%%251%%179%%198%: SMD陶瓷电容; CODE: 8070649; COMPONENT_HIGH_MAX: 0.9MM; DEVICE: C1608X5R0J106MT0A0E
LB12 = LB: %195%%232%%202%%246%: EMI磁珠-+/-25%-1000OHM-1.25OHM-0.25A-0402-1400OHM@1GHZ; %208%%161%%192%%224%%195%%251%%179%%198%: EMI磁珠; CODE: 10070019; COMPONENT_HIGH_MAX: 0.65MM; DEVICE: BLM15HG102SN1D
R32 = R: %182%%238%%182%%168%%185%%166%%194%%202%(W): 0.06; %195%%232%%202%%246%: 片式厚膜电阻器-0.0625W-12000OHM-+/-1%-0402; %208%%161%%192%%224%%195%%251%%179%%198%: 片式厚膜电阻器; %215%%232%%214%%181%%212%%202%%208%%237%%198%%171%%178%%238%: +/-1%; CODE: 7090817; DEVICE: RC0402FR_0712K
S1 = MSW2S5: %195%%232%%202%%246%: 微动开关-SPST-12VDC-0.05A0.4MM-3.5*2.9*1.55MM-终端专用-00822481; CODE: 16100071; COMPONENT_HIGH_MAX: 1.75MM; DEVICE: LS12T2_T
C19 C97 C109 C117 C243 = C: %182%%238%%182%%168%%185%%164%%215%%247%%181%%231%%209%%185%(V): 6.3; %195%%232%%202%%246%: SMD陶瓷电容-6.3V-470NF-+/-10%-X5R-0402; %208%%161%%192%%224%%195%%251%%179%%198%: SMD陶瓷电容; CODE: 8070625; COMPONENT_HIGH_MAX: 0.55MM; DEVICE: GRM155R60J474KE19D
LB7 LB21 LB22 = LB: %195%%232%%202%%246%: EMI磁珠-25%-600OHM-1OHM-0.2A-0603-700OHM TYP@1GHZ; %208%%161%%192%%224%%195%%251%%179%%198%: EMI磁珠; CODE: 10070016; COMPONENT_HIGH_MAX: 0.95MM; DEVICE: BLM18HG601SN1D
R45 R46 = R: %182%%238%%182%%168%%185%%166%%194%%202%(W): 0.06; %195%%232%%202%%246%: 片式厚膜电阻器-0.0625W-240OHM-+/- 1%-0402-BT; %208%%161%%192%%224%%195%%251%%179%%198%: 片式厚膜电阻器; %215%%232%%214%%181%%212%%202%%208%%237%%198%%171%%178%%238%: +/- 1%; CODE: 7091782; COMPONENT_HIGH_MAX: 0.4MM; DEVICE: RC0402FR_07240RL
C86 C87 = C: %182%%238%%182%%168%%185%%164%%215%%247%%181%%231%%209%%185%(V): 6.3; %195%%232%%202%%246%: SMD陶瓷电容-6.3V-22000NF-+/-20%-X5R-1206-BT,TS16949; %208%%161%%192%%224%%195%%251%%179%%198%: SMD陶瓷电容; CODE: 8070630; COMPONENT_HIGH_MAX: 1.9MM; DEVICE: GRM31CR60J226ME19L
C313 = C: %182%%238%%182%%168%%185%%164%%215%%247%%181%%231%%209%%185%(V): 50; %195%%232%%202%%246%: SMD陶瓷电容-50V-1NF-+/-10%-X7R-0402-BT; %208%%161%%192%%224%%195%%251%%179%%198%: SMD陶瓷电容; CODE: 8070531; COMPONENT_HIGH_MAX: 0.56MM; DEVICE: 04025C102KAT2A
C328 = C: %182%%238%%182%%168%%185%%164%%215%%247%%181%%231%%209%%185%(V): 16; %195%%232%%202%%246%: SMD陶瓷电容-16V-10NF-+/-10%-X7R-0402-BT,TS16949; %208%%161%%192%%224%%195%%251%%179%%198%: SMD陶瓷电容; CODE: 8070449; COMPONENT_HIGH_MAX: 0.56MM; DEVICE: GRM155R71C103KA01D
R11 R15 = R: %195%%232%%202%%246%: 片式厚膜电阻器-0.0625W-100OHM-±5%-0402; CODE: 7090807; COMPONENT_HIGH_MAX: 0.4MM; DEVICE: RC0402JR_07100R
R51 R54 R55 R75 = R: %182%%238%%182%%168%%185%%166%%194%%202%(W): 0.06; %195%%232%%202%%246%: 片式厚膜电阻器-0.0625W-1000OHM-+/-1%-0402-BT; %208%%161%%192%%224%%195%%251%%179%%198%: 片式厚膜电阻器; %215%%232%%214%%181%%212%%202%%208%%237%%198%%171%%178%%238%: +/-1%; CODE: 7091282; COMPONENT_HIGH_MAX: 0.4MM; DEVICE: RC0402FR_071KL
RN1-RN7 = RND8-4_5: %195%%232%%202%%246%: 电阻网络-0.0625W-33OHM-4个-8PIN-±5%-SMT-小型-独立式-2.0*1.0*0.45-0.5MM; %208%%161%%192%%224%%195%%251%%179%%198%: 电阻网络; %215%%232%%214%%181%%212%%202%%208%%237%%198%%171%%178%%238%: ±5%; CODE: 7080118; COMPONENT_HIGH_MAX: 0.55MM; DEVICE: YC124_JR_0733R
U3 = MT41J256M16RE-15E-D_4: %195%%232%%202%%246%: DDR3 DRAM-4GBIT-800MHZ-16BIT-1.5V-FBGA96(无铅); %208%%161%%192%%224%%195%%251%%179%%198%: DDR3 DRAM; CODE: 40020173; COMPONENT_HIGH_MAX: -99999999MM; DEVICE: H5TQ4G63MFR_PBC_A

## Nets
1V1_CORE: C1.1(A) C19.1(A) C62.1(A) C64.1(A) C66.1(A) C70.1(A) C73.1(A) C87.1(A) C107.1(A) C120.1(A) C121.1(A) C126.1(A) C127.1(A) C128.1(A) C129.1(A) C130.1(A) C189.1(A) C193.1(A) C282.1(A) LB12.2 LB21.1 LB31.1(A) U1.4(VDD_1) U1.10(VDD_2) U1.30(VDD_3) U1.39(VDD_4) U1.49(VDD_5) U1.78(VDD_6) U1.86(VDD_7) U1.105(VDD_8) U1.118(VDD_9) U1.134(VDD_10) U1.158(VDD_11) U1.168(VDD_12) U1.180(VDD_13) U1.186(VDD_14) U1.193(VDD_15) U1.202(VDD_16) U1.214(VDD_17) ; also on sheet 15
1V1_CPU: C16.1(A) C31.1(A) C34.1(A) C38.1(A) C42.1(A) C75.1(A) C81.1(A) C86.1(A) C132.1(A) C242.1(A) C243.1(A) C257.1(A) U1.91(VDD_CPU_0) U1.92(VDD_CPU_1) U1.93(VDD_CPU_2) U1.95(VDD_CPU_3) U1.96(VDD_CPU_4) U1.98(VDD_CPU_5) ; also on sheet 15
1V5_DDR3: C20.1(A) C48.1(A) C49.1(A) C52.1(A) C92.1(A) C94.1(A) C96.1(A) C97.1(A) C98.1(A) C99.1(A) C101.1(A) C102.1(A) C104.1(A) C109.1(A) C117.1(A) C125.1(A) C131.1(A) C137.1(A) C203.1(A) C206.1(A) C207.1(A) C208.1(A) C211.1(A) C212.1(A) C213.1(A) C214.1(A) C215.1(A) C216.1(A) C218.1(A) C219.1(A) C220.1(A) C315.1(A) R51.1(A) R54.1(A) R60.1(A) U1.1(VDDIO_DDR0) U1.7(VDDIO_DDR1) U1.13(VDDIO_DDR2) U1.16(VDDIO_DDR_CK) U1.25(VDDIO_DDR3) U1.35(VDDIO_DDR4) U1.44(VDDIO_DDR5) U1.53(VDDIO_DDR6) U1.165(VDDIO_DDR7) U1.171(VDDIO_DDR8) U1.174(VDDIO_DDR9) U1.183(VDDIO_DDR10) U1.190(VDDIO_DDR11) U1.196(VDDIO_DDR12) U1.199(VDDIO_DDR13) U1.205(VDDIO_DDR14) U1.208(VDDIO_DDR15) U3.A1(VDDQ1) U3.A8(VDDQ2) U3.B2(VDD1) U3.C1(VDDQ3) U3.C9(VDDQ4) U3.D2(VDDQ5) U3.D9(VDD2) U3.E9(VDDQ6) U3.F1(VDDQ7) U3.G7(VDD3) U3.H2(VDDQ8) U3.H9(VDDQ9) U3.K2(VDD4) U3.K8(VDD5) U3.N1(VDD6) U3.N9(VDD7) U3.R1(VDD8) U3.R9(VDD9) ; also on sheet 8 15
3V3: C13.1(A) C108.1(A) LB5.1 Q13.2(S) R88.2(B) ; also on sheet 3 5 15
3V3_MOS: C74.1(A) C197.1(A) C198.1(A) C199.1(A) C245.1(A) C283.1(A) LB1.2(B) LB7.2 LB8.2(B) LB14.1(A) LB17.1(A) LB20.1(A) LB22.1 Q13.3(D) R25.1(A) R39.2(B) R41.2(B) U1.74(DVDD3318_0) U1.83(DVDD3318_1) U1.104(DVDD33_0) U1.120(DVDD33_1) ; also on sheet 1 2 3 6 7
5V0: C6.1(A) Q14.2(S) R144.1(A) ; also on sheet 15
5V0_MOS: Q14.3(D) ; also on sheet 1 4 6
AVDD11_PLL012: C12.1(A) C185.1(A) LB21.2 U1.68(AVDD11_PLL)
AVDD33_PLL01: C14.1(A) C186.1(A) LB22.2 U1.66(AVDD33_PLL)
AVDD33_USB2: C3.1(A) C95.1(A) LB17.2(B) U1.88(AVDD33_USB)
GND: C1.2(B) C3.2(B) C7.2(B) C9.2(B) C10.2(B) C11.2(B) C12.2(B) C13.2(B) C14.2(B) C16.2(B) C18.2(B) C19.2(B) C20.2(B) C31.2(B) C34.2(B) C38.2(B) C42.2(B) C48.2(B) C49.2(B) C52.2(B) C57.2(B) C62.2(B) C64.2(B) C66.2(B) C70.2(B) C73.2(B) C74.2(B) C75.2(B) C77.2(B) C78.2(B) C81.2(B) C85.2(B) C86.2(B) C87.2(B) C92.2(B) C94.2(B) C95.2(B) C96.2(B) C97.2(B) C98.2(B) C99.2(B) C101.2(B) C102.2(B) C104.2(B) C107.2(B) C108.2(B) C109.2(B) C113.2(B) C117.2(B) C118.2(B) C119.2(B) C120.2(B) C121.2(B) C122.2(B) C125.2(B) C126.2(B) C127.2(B) C128.2(B) C129.2(B) C130.2(B) C131.2(B) C132.2(B) C136.2(B) C137.2(B) C138.1(A) C164.2(B) C182.2(B) C185.2(B) C186.2(B) C189.2(B) C193.2(B) C197.2(B) C198.2(B) C199.2(B) C203.2(B) C206.2(B) C211.2(B) C212.2(B) C213.2(B) C214.2(B) C215.2(B) C216.2(B) C218.2(B) C219.2(B) C220.2(B) C242.2(B) C243.2(B) C245.2(B) C248.2(B) C250.1(A) C255.1(A) C257.2(B) C264.2(B) C270.2(B) C271.2(B) C281.2(B) C282.2(B) C283.2(B) C289.2(B) C313.2(B) C315.2(B) C328.2(B) C334.2(B) C336.2(B) C364.2(B) C365.2(B) Q4.2(E) R24.1(A) R32.1(A) R33.2(B) R38.1(A) R40.2(B) R45.2(B) R46.1(A) R55.2(B) R56.1(A) R75.2(B) R82.1(A) R85.1(A) R87.1(A) R173.2(B) RN1.3 RN1.6 RN2.3 RN2.6 RN3.2 RN3.7 RN4.3 RN4.6 RN5.2 RN5.7 RN6.3 RN6.6 RN7.2 RN7.7 S1.1(P1) S1.3(S1) S1.4(S2) S1.5(S3) S1.6(S4) S1.7(S5) S2.3 S2.4 S2.5 S2.6 U1.19(DDR_VSS0) U1.62(VSS_1) U1.67(AVSS_PLL) U1.94(VSS_2) U1.97(VSS_3) U1.110(AVSS_VDAC) U1.115(AVSS_ADAC) U1.177(DDR_VSS1) U1.211(DDR_VSS2) U1.217(VSS_EPAD) U3.A9(VSS1) U3.B1(VSSQ1) U3.B3(VSS2) U3.B9(VSSQ2) U3.D1(VSSQ3) U3.D8(VSSQ4) U3.E1(VSS3) U3.E2(VSSQ5) U3.E8(VSSQ6) U3.F9(VSSQ7) U3.G1(VSSQ8) U3.G8(VSS4) U3.G9(VSSQ9) U3.J2(VSS5) U3.J8(VSS6) U3.M1(VSS7) U3.M9(VSS8) U3.P1(VSS9) U3.P9(VSS10) U3.T1(VSS11) U3.T9(VSS12) X2.2(GND1) X2.4(GND2) ; also on sheet 1 2 3 4 5 6 7 8 15 16
ADAC_VOUTL: U1.114(ADAC_VOUTL) ; also on sheet 4
ADAC_VOUTR: U1.116(ADAC_VOUTR) ; also on sheet 4
CORE_CTRL: U1.106(PWM0/I2C2_SCL/GPIO2_6) ; also on sheet 15
CPU_CTRL: U1.107(PWM1/I2C2_SDA/GPIO2_7) ; also on sheet 15
CVBS: U1.109(VDAC_0) ; also on sheet 2
DDR_ADDR0: RN2.1 U1.43(DDR_A0) ; also on sheet 8
DDR_ADDR0_A: RN2.8 U3.N3(A0)
DDR_ADDR1: RN4.4 U1.27(DDR_A1) ; also on sheet 8
DDR_ADDR1_A: RN4.5 U3.P7(A1)
DDR_ADDR2: R62.1(A) U1.45(DDR_A2) ; also on sheet 8
DDR_ADDR2_A: R62.2(B) U3.P3(A2)
DDR_ADDR3: RN2.2 U1.42(DDR_A3) ; also on sheet 8
DDR_ADDR3_A: RN2.7 U3.N2(A3)
DDR_ADDR4: R64.1(A) U1.26(DDR_A4) ; also on sheet 8
DDR_ADDR4_A: R64.2(B) U3.P8(A4)
DDR_ADDR5: RN2.4 U1.51(DDR_A5) ; also on sheet 8
DDR_ADDR5_A: RN2.5 U3.P2(A5)
DDR_ADDR6: RN4.2 U1.28(DDR_A6) ; also on sheet 8
DDR_ADDR6_A: RN4.7 U3.R8(A6)
DDR_ADDR7: R61.1(A) U1.50(DDR_A7) ; also on sheet 8
DDR_ADDR7_A: R61.2(B) U3.R2(A7)
DDR_ADDR8: RN4.1 U1.29(DDR_A8) ; also on sheet 8
DDR_ADDR8_A: RN4.8 U3.T8(A8)
DDR_ADDR9: RN1.2 U1.37(DDR_A9) ; also on sheet 8
DDR_ADDR9_A: RN1.7 U3.R3(A9)
DDR_ADDR10: RN6.4 U1.22(DDR_A10) ; also on sheet 8
DDR_ADDR10_A: RN6.5 U3.L7(A10/AP)
DDR_ADDR11: RN5.3 U1.32(DDR_A11) ; also on sheet 8
DDR_ADDR11_A: RN5.6 U3.R7(A11)
DDR_ADDR12: RN6.2 U1.23(DDR_A12) ; also on sheet 8
DDR_ADDR12_A: RN6.7 U3.N7(A12/BC~)
DDR_ADDR13: RN1.4 U1.46(DDR_A13) ; also on sheet 8
DDR_ADDR13_A: RN1.5 U3.T3(A13)
DDR_ADDR14: RN5.4 U1.31(DDR_A14) ; also on sheet 8
DDR_ADDR14_A: RN5.5 U3.T7(A14)
DDR_ADDR15: RN5.1 U1.36(DDR_A15) ; also on sheet 8
DDR_ADDR15_A: RN5.8 U3.M7(NC5)
DDR_BA0: RN7.4 U1.47(DDR_BA0) ; also on sheet 8
DDR_BA0_A: RN7.5 U3.M2(BA0)
DDR_BA1: RN6.1 U1.24(DDR_BA1) ; also on sheet 8
DDR_BA1_A: RN6.8 U3.N8(BA1)
DDR_BA2: RN3.1 U1.33(DDR_BA2) ; also on sheet 8
DDR_BA2_A: RN3.8 U3.M3(BA2)
DDR_CASN: RN3.4 U1.40(DDR_CAS_N) ; also on sheet 8
DDR_CASN_A: RN3.5 U3.K3(~{CAS})
DDR_CKE: R38.2(B) R65.1(A) U1.21(DDR_CKE) ; also on sheet 8
DDR_CKE_A: R65.2(B) U3.K9(CKE)
DDR_CLK0N: R11.1(A) R35.1(A) U3.K7(~{CK})
DDR_CLK0P: R15.2(B) R18.1(A) U3.J7(CK)
DDR_CLK1N: R37.1(A) ; also on sheet 8
DDR_CLK1P: R36.1(A) ; also on sheet 8
DDR_CSN: R63.1(A) U1.34(DDR_CSN) ; also on sheet 8
DDR_CSN_A: R63.2(B) U3.L2(~{CS})
DDR_DM0: U1.181(DDR_DM0) U3.E7(LDM)
DDR_DM1: U1.182(DDR_DM1) U3.D3(UDM)
DDR_DM2: U1.215(DDR_DM2) ; also on sheet 8
DDR_DM3: U1.216(DDR_DM3) ; also on sheet 8
DDR_DQ0: U1.167(DDR_DQ0) U3.E3(DQ0)
DDR_DQ1: U1.191(DDR_DQ1) U3.F7(DQ1)
DDR_DQ2: U1.164(DDR_DQ2) U3.F2(DQ2)
DDR_DQ3: U1.192(DDR_DQ3) U3.F8(DQ3)
DDR_DQ4: U1.166(DDR_DQ4) U3.H3(DQ4)
DDR_DQ5: U1.195(DDR_DQ5) U3.H8(DQ5)
DDR_DQ6: U1.163(DDR_DQ6) U3.G2(DQ6)
DDR_DQ7: U1.194(DDR_DQ7) U3.H7(DQ7)
DDR_DQ8: U1.184(DDR_DQ8) U3.D7(DQ8)
DDR_DQ9: U1.170(DDR_DQ9) U3.C3(DQ9)
DDR_DQ10: U1.185(DDR_DQ10) U3.C8(DQ10)
DDR_DQ11: U1.169(DDR_DQ11) U3.C2(DQ11)
DDR_DQ12: U1.188(DDR_DQ12) U3.A7(DQ12)
DDR_DQ13: U1.172(DDR_DQ13) U3.A2(DQ13)
DDR_DQ14: U1.189(DDR_DQ14) U3.B8(DQ14)
DDR_DQ15: U1.173(DDR_DQ15) U3.A3(DQ15)
DDR_DQ16: U1.201(DDR_DQ16) ; also on sheet 8
DDR_DQ17: U1.8(DDR_DQ17) ; also on sheet 8
DDR_DQ18: U1.198(DDR_DQ18) ; also on sheet 8
DDR_DQ19: U1.9(DDR_DQ19) ; also on sheet 8
DDR_DQ20: U1.200(DDR_DQ20) ; also on sheet 8
DDR_DQ21: U1.12(DDR_DQ21) ; also on sheet 8
DDR_DQ22: U1.197(DDR_DQ22) ; also on sheet 8
DDR_DQ23: U1.11(DDR_DQ23) ; also on sheet 8
DDR_DQ24: U1.6(DDR_DQ24) ; also on sheet 8
DDR_DQ25: U1.204(DDR_DQ25) ; also on sheet 8
DDR_DQ26: U1.5(DDR_DQ26) ; also on sheet 8
DDR_DQ27: U1.203(DDR_DQ27) ; also on sheet 8
DDR_DQ28: U1.2(DDR_DQ28) ; also on sheet 8
DDR_DQ29: U1.206(DDR_DQ29) ; also on sheet 8
DDR_DQ30: U1.3(DDR_DQ30) ; also on sheet 8
DDR_DQ31: U1.207(DDR_DQ31) ; also on sheet 8
DDR_DQS0N: U1.176(~{DDR_DQS0_N}) U3.G3(~{LDQS})
DDR_DQS0P: U1.175(DDR_DQS0_P) U3.F3(LDQS)
DDR_DQS1N: U1.179(~{DDR_DQS1_N}) U3.B7(~{UDQS})
DDR_DQS1P: U1.178(DDR_DQS1_P) U3.C7(UDQS)
DDR_DQS2N: U1.210(~{DDR_DQS2_N}) ; also on sheet 8
DDR_DQS2P: U1.209(DDR_DQS2_P) ; also on sheet 8
DDR_DQS3N: U1.213(~{DDR_DQS3_N}) ; also on sheet 8
DDR_DQS3P: U1.212(DDR_DQS3_P) ; also on sheet 8
DDR_ODT: RN7.3 U1.48(DDR_ODT) ; also on sheet 8
DDR_ODT_A: RN7.6 U3.K1(ODT)
DDR_PLL: C11.1(A) C264.1(A) C270.1(A) LB7.1 U1.20(AVDD_DDRPLL2) U1.187(AVDD_DDRPLL1)
DDR_RASN: RN7.1 U1.52(DDR_RAS_N) ; also on sheet 8
DDR_RASN_A: RN7.8 U3.J3(~{RAS})
DDR_RESETN: RN1.1 U1.38(DDR3_RESET_N) ; also on sheet 8
DDR_RESETN_A: C313.1(A) R60.2(B) RN1.8 U3.T2(~{RESET})
DDR_VREF_CA_A: C207.2(B) C289.1(A) R51.2(B) R55.1(A) U3.M8(VREFCA)
DDR_VREF_DQ_A: C208.2(B) C271.1(A) R54.2(B) R75.1(A) U3.H1(VREFDQ)
DDR_WEN: RN3.3 U1.41(DDR_WE_N) ; also on sheet 8
DDR_WEN_A: RN3.6 U3.L3(~{WE})
FE_1V1: C248.1(A) U1.147(AVDD11_FE_0)
FE_3V3: C7.1(A) C18.1(A) LB8.1(A) U1.144(AVDD33_FE_0) U1.148(AVDD33_FE_1)
HDMI_TX0N: U1.126(HDMI_TX0N) ; also on sheet 1
HDMI_TX0P: U1.127(HDMI_TX0P) ; also on sheet 1
HDMI_TX1N: U1.130(HDMI_TX1N) ; also on sheet 1
HDMI_TX1P: U1.131(HDMI_TX1P) ; also on sheet 1
HDMI_TX2N: U1.132(HDMI_TX2N) ; also on sheet 1
HDMI_TX2P: U1.133(HDMI_TX2P) ; also on sheet 1
HDMI_TX_1V1: C78.1(A) C113.1(A) C164.1(A) C281.1(A) LB12.1 U1.128(HDMITX_AVCC11)
HDMI_TX_3V3: C57.1(A) C77.1(A) LB1.1(A) U1.129(HDMITX_AVDD33)
HDMI_TX_CEC: U1.123(GPIO4_7/HDMI_TX_CEC) ; also on sheet 1
HDMI_TX_HOTPLUG: U1.119(GPIO4_6/HDMI_TX_HOTPLUG) ; also on sheet 1
HDMI_TX_SCL: U1.122(GPIO4_5/HDMI_TX_SCL) ; also on sheet 1
HDMI_TX_SDA: U1.121(GPIO4_4/HDMI_TX_SDA) ; also on sheet 1
HDMI_TXCN: U1.124(HDMI_TXCN) ; also on sheet 1
HDMI_TXCP: U1.125(HDMI_TXCP) ; also on sheet 1
IR_IN: U1.58(GPIO5_1/IR_IN) ; also on sheet 5
LED0_BASE: U1.151(GPIO2_2/FE_LED_BASE) ; also on sheet 3
LED0_LINK_ACT: U1.150(GPIO2_1/FE_LED_ACT) ; also on sheet 3
LED_CTRL: U1.57(GPIO5_2/LED_KEY0) ; also on sheet 5
NF_ALE_EMMC_PWREN: U1.80(NF_ALE/SDIO1_CARD_POWER_EN/GPIO0_1) ; also on sheet 7
NF_CLE: U1.81(NF_CLE/SDIO_CWPR/GPIO0_2) ; also on sheet 7
NF_CSN0_EMMC_CMD: U1.82(NF_CSN0/SDIO1_CCMD) ; also on sheet 7
NF_DQ0_EMMC_D0: U1.77(EBI_DQ0/SDIO1_CDATA0) ; also on sheet 7
NF_DQ1_EMMC_D1: U1.76(EBI_DQ1/SDIO1_CDATA1) ; also on sheet 7
NF_DQ2_EMMC_D2: U1.75(EBI_DQ2/SDIO1_CDATA2) ; also on sheet 7
NF_DQ3_EMMC_D3: U1.73(EBI_DQ3/SDIO1_CDATA3) ; also on sheet 7
NF_DQ4_EMMC_D4: U1.72(EBI_DQ4/SDIO1_CDATA4) ; also on sheet 7
NF_DQ5_EMMC_D5: U1.71(EBI_DQ5/SDIO1_CDATA5) ; also on sheet 7
NF_DQ6_EMMC_D6: U1.70(EBI_DQ6/SDIO1_CDATA6) ; also on sheet 7
NF_DQ7_EMMC_D7_BOOT_SEL0: R33.1(A) U1.69(EBI_DQ7/SDIO1_CDATA7/BOOT_SEL0) ; also on sheet 7
NF_RDY0_EMMC_RST: U1.85(NF_RDY0/SDIO1_RST) ; also on sheet 7
NF_REN_EMMC_CLK: R59.1(A) ; also on sheet 7
NF_WEN_EMMC_DET: R56.2(B) U1.79(NF_WEN/SDIO1_CARD_DETECT/GPIO0_0) ; also on sheet 7
PWR_OFF/ON: R40.1(A) R41.1(A) U1.102(JTAG_TDI/GPIO0_7)
RECOVERY: C138.2(B) R25.2(B) S1.2(P2) U1.103(JTAG_TDO/GPIO2_0)
RX+_PHY0: U1.143(FE_RXP) ; also on sheet 3
RX-_PHY0: U1.142(FE_RXN) ; also on sheet 3
SPDIF_OUT_BOOT_SEL1: R39.1(A) U1.117(BOOT_SEL1/GPIO4_2/SPDIF_OUT)
STANDBY_PWROFF: C119.1(A) LB3.2 R88.1(A) R98.1(A) ; also on sheet 15
TX+_PHY0: U1.146(FE_TXP) ; also on sheet 3
TX-_PHY0: U1.145(FE_TXN) ; also on sheet 3
UART0_RXD: U1.60(UART1_RXD/UART0_RXD) ; also on sheet 3
UART0_TXD: U1.61(UART1_TXD/UART0_TXD) ; also on sheet 3
USB0_DM: U1.140(USB0_DM) ; also on sheet 6
USB0_DP: U1.141(USB0_DP) ; also on sheet 6
USB01_1V1: C334.1(A) C336.1(A) LB31.2(B) U1.137(AVCC11_USB)
USB01_3V3: C10.1(A) C182.1(A) LB20.2(B) U1.139(AVDD33_USB)
USB1_DM: U1.135(USB1_DM) ; also on sheet 6
USB1_DP: U1.136(USB1_DP) ; also on sheet 6
USB2_DM: U1.89(USB2_DM) ; also on sheet 6
USB2_DP: U1.90(USB2_DP) ; also on sheet 6
USB_BOOT: R42.2(B) U1.108(USB_BOOT/GPIO2_5)
VDAC_3V3: C9.1(A) C85.1(A) LB14.2(B) U1.112(AVDD33_VDAC)
XIN: C364.1(A) R1.2(B) U1.63(XIN) X2.1
XOUT: R1.1(A) R14.1(A) U1.64(XOUT)
N341925: C6.2(B) Q13.1(G) Q14.1(G) R118.1(A)
N341969: Q4.1(B) R98.2(B)
N342021: Q4.3(C) R118.2(B) R144.2(B)
N351495: C136.1(A) R42.1(A) S2.1 S2.2
N351535: C365.1(A) R14.2(B) X2.3
N351659: R82.2(B) R85.2(B) U1.138(USB01_REXT)
N351675: R173.1(A) U1.149(FE_REXT)
N351797: R59.2(B) U1.84(NF_REN/SDIO1_CCLK_OUT)
N351801: C118.1(A) LB3.1 U1.59(GPIO5_0/STANDBY_POWER_OFF)
N362136: C250.2(B) U1.113(ADAC_VREFDAC)
N362152: R32.2(B) U1.111(VDAC_IREF)
N362162: R24.2(B) R87.2(B) U1.87(USB2_RBIAS)
N379314: R45.1(A) U1.54(ZQ)
N379318: R37.2(B) U1.15(~{DDR_CLK1_N})
N379322: R36.2(B) U1.14(DDR_CLK1_P)
N379326: R35.2(B) U1.18(~{DDR_CLK0_N})
N379330: R18.2(B) U1.17(DDR_CLK0_P)
N390012: C328.1(A) R11.2(B) R15.1(A)
N390480: R46.2(B) U3.L8(ZQ)
N395473: C255.2(B) U1.55(DVDD11_LDO1_OUT)
N395477: C122.1(A) LB5.2 U1.65(DVDD33_STANDBY_0)

Not connected (* = marked no-connect by the designer): U1 56(FUNC_SEL) 99(JTAG_TMS/GPIO0_4) 100(JTAG_RST/GPIO0_5) 101(JTAG_TCK/GPIO0_6) 152(GPIO2_3/SDIO0_CWPR) 153(GPIO3_0/SDIO0_CDATA1) 154(GPIO3_1/SDIO0_CDATA0) 155(CAPACITOR_LDO) 156(GPIO3_2/SDIO0_CCLK_OUT) 157(GPIO3_3/SDIO0_CCMD) 159(GPIO3_4/SDIO0_CDATA3) 160(GPIO3_5/SDIO0_CDATA2) 161(GPIO3_6/SDIO0_CARD_DETECT) 162(GPIO3_7/SDIO0_CARD_POWER_EN); U3 J1(NC1) J9(NC2) L1(NC3) L9(NC4)

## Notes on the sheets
sheet 9
- DDRA
- 1%
- 1%
- 1%
- 1%
- 1%
- 1%
- 1%
- The type and specification of the components  refer to the BOM
- NA
- 2014-07-22
- ECA NO
- DATE
- DESIGNED
- XIONGLIN 00282668
- HI3798MDMO1F_VERC
- 00001234
- REVIEWED
- CHENYUZHU 149603
- VER
- PART_NUMBER
- SHEET
- 10
- OF
- 18
- A
- 03030001
- HUAWEI TECH CO.,LTD.
sheet 10
- Unit 4 of Hi3798MV100(POWER)
- The type and specification of the components  refer to the BOM
- NA
- 2014-07-22
- ECA NO
- DATE
- DESIGNED
- XIONGLIN 00282668
- HI3798MDMO1F_VERC
- 00001234
- REVIEWED
- CHENYUZHU 149603
- VER
- PART_NUMBER
- SHEET
- 9
- OF
- 18
- A
- 03030001
- HUAWEI TECH CO.,LTD.
sheet 11
- Unit 3 of Hi3798MV100(DDR)
- 1%
- Close to Hi3798M
- ** DDR Design guideline **
- The type and specification of the components  refer to the BOM
- A.general suggestion
- 1.Hi3798MV100 supports up to 2GB DDR3.
- NA
- 2014-07-22
- 2.DDR chip and DDR controller both need at least one 10uF decoupling ceramic capacitor.
- ECA NO
- DATE
- 3.The ciruit of DDR_VREF_CA and DDR_VREF_DQ must be independent
- DESIGNED
- XIONGLIN 00282668
- 4. 3V3 DDRPLL is needed.
- 00001234
- HI3798MDMO1F_VERC
- B.Layout suggestion
- REVIEWED
- CHENYUZHU 149603
- 1. Please copy hisilicon demo board completely
- VER
- PART_NUMBER
- SHEET
- 8
- OF
- 18
- A
- 03030001
- HUAWEI TECH CO.,LTD.
sheet 12
- Unit 2 of Hi3798MV100(USB/VDAC/HDMI TX/UART/SPDIF/ADAC/LED/IR)
- ** Audio & Video Design guideline **
- A.VIDEO
- 1.VIDEO REXT resistor should be 12K +/-1% precision.
- 2.REXT/COMP should be traced as short as possible,
- and isolated from all other traces.
- B.AUDIO
- 1.VREF should be traced as short as possible,
- and isolated from all other traces.
- 1%
- 135ohm
- NOTE:EMI-1000ohm
- or 600ohm@100MHz
- 1%
- R40=10k,R41=NC:power up-->pull key-->start
- R40=NC,R41=10k:power up-->start
- ** USB Design guideline **
- A.routing
- 1.Route as 90 Ohm differential impedance.
- 2.Differential pairs should be routed on TOP layer only.
- 3.Differential pairs should be separated from other traces by GND .
- The type and specification of the components  refer to the BOM
- B.trace length
- 1.The length for the differential pairs should be less than 5 inches.
- NA
- 2014-07-22
- 2.Match trace length of DP and DM differential pairs, 10 mils max within a pair.
- ECA NO
- DATE
- C.component selection
- DESIGNED
- XIONGLIN 00282668
- 1.USB2.0 REXT resistor should be 135 ohm +/-1% and USB3.0 200 ohm +/-1%.
- HI3798MDMO1F_VERC
- 00001234
- 2.ESD components are suggested for ports protection.
- 3.Equivalent capacitance of ESD component should be < 1.5pF.
- REVIEWED
- CHENYUZHU 149603
- VER
- PART_NUMBER
- SHEET
- 7
- OF
- 18
- A
- 03030001
- HUAWEI TECH CO.,LTD.
sheet 13
- Unit 1 of Hi3798MV100(EMMC/NAND/USB/XTAL/FE)
- 2 Layers
- R59=33ohm
- Close to Hi3798M
- 1%
- 135ohm
- 1%
- USB0:usb_boot/adb
- System Oscillator
- PD
- PU
- ** FE PHY Design guideline **
- BOOT DEVICE SEL
- BOOT_SEL[1:0]
- A.routing
- BOOT_SEL1
- PD
- 11:eMMC
- 01:NAND Flash
- 1.Route as 100 Ohm differential impedance.
- BOOT_SEL0
- PU
- 10:fSD
- 2.Differential pairs should be routed on TOP layer only.
- 3.Differential pairs should be separated from other traces by GND .
- The type and specification of the components  refer to the BOM
- B.trace length
- 1.The length for the differential pairs should be less than 5 inches.
- NA
- 2014-07-22
- 2.Match trace length of RX and TX differential pairs, 10 mils max within a pair.
- ECA NO
- DATE
- C.component selection
- DESIGNED
- XIONGLIN 00282668
- 1.REXT resistor should be 10K ohm +/-1%.
- HI3798MDMO1F_VERC
- 00001234
- 2.ESD components are suggested for ports protection,
- Put between Hi398MV100 and transformer.
- REVIEWED
- CHENYUZHU 149603
- VER
- PART_NUMBER
- SHEET
- 6
- OF
- 18
- A
- 03030001
- HUAWEI TECH CO.,LTD.
sheet 14
- Power Ctrl
- STANDBY_PWROFF
- 0
- Power Off
- 1
- Power On
- The type and specification of the components  refer to the BOM
- NA
- 2014-07-22
- ECA NO
- DATE
- DESIGNED
- XIONGLIN 00282668
- HI3798MDMO1F_VERC
- 00001234
- REVIEWED
- CHENYUZHU 149603
- VER
- PART_NUMBER
- SHEET
- 5
- OF
- 18
- A
- 03030001
- HUAWEI TECH CO.,LTD.
